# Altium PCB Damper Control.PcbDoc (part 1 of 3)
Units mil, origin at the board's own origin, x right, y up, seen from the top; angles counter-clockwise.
Board outline 4586.61 x 2962.6 mil, 4 copper layers (Top Layer, GND Plane, Power Plane, Bottom Layer), stack 70.356 mil thick; 195 components, 143 nets, 589 pads, 854 vias.
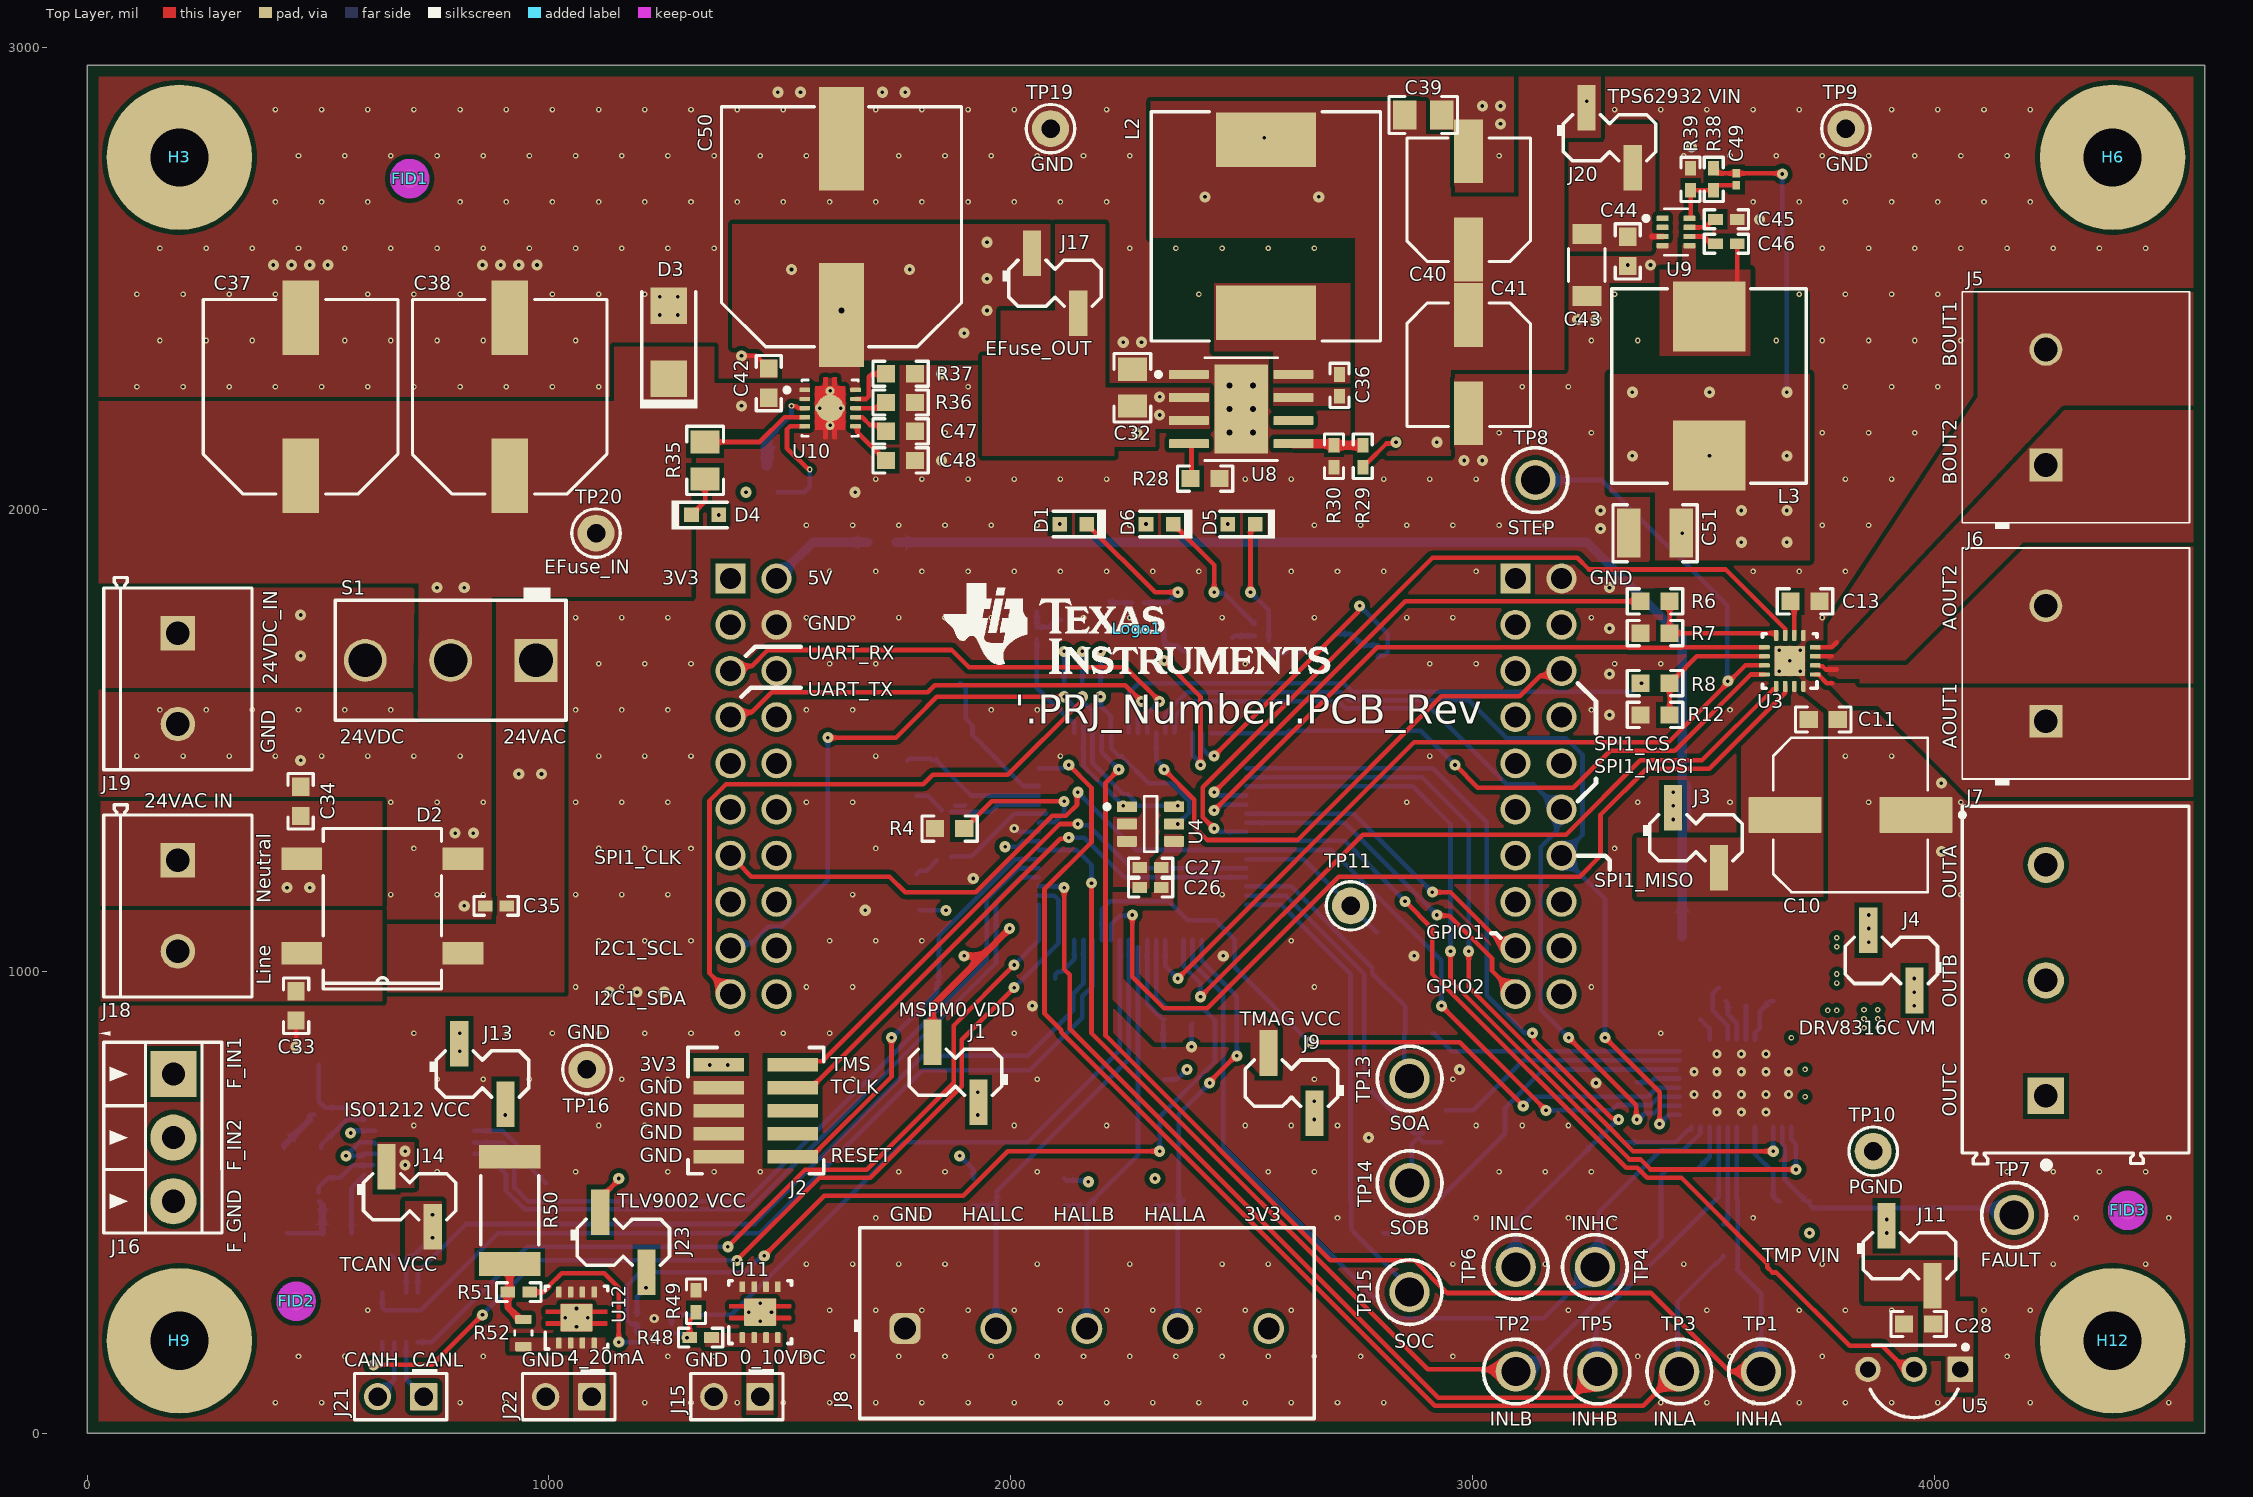
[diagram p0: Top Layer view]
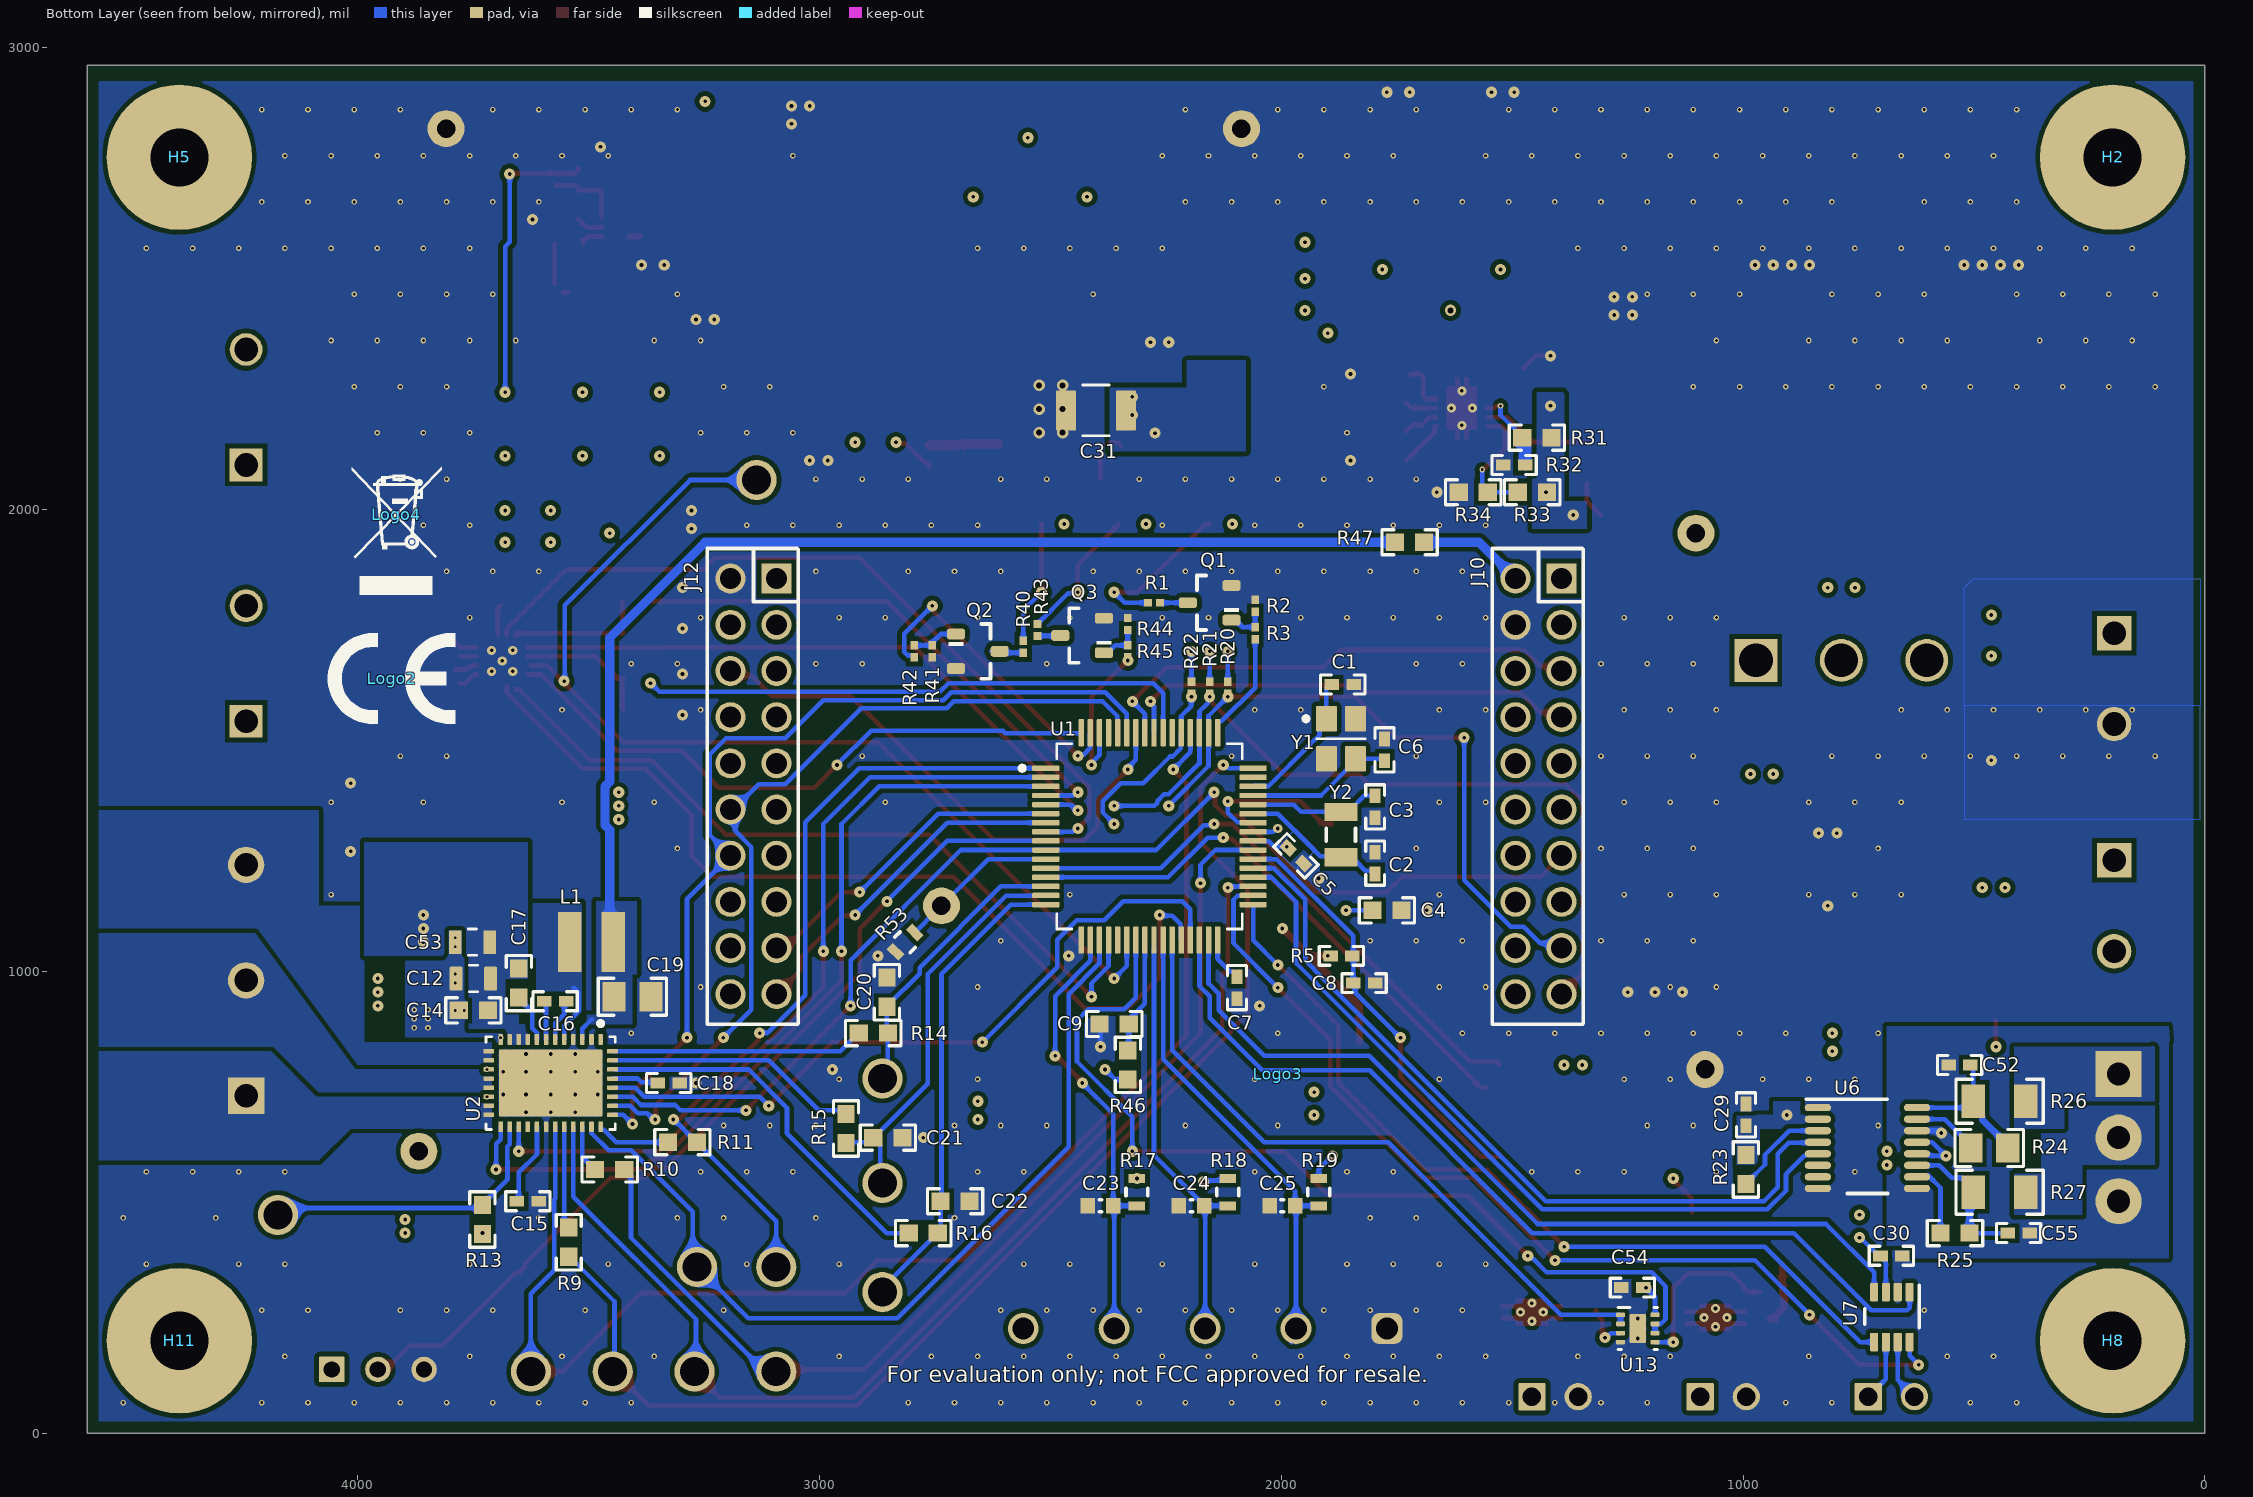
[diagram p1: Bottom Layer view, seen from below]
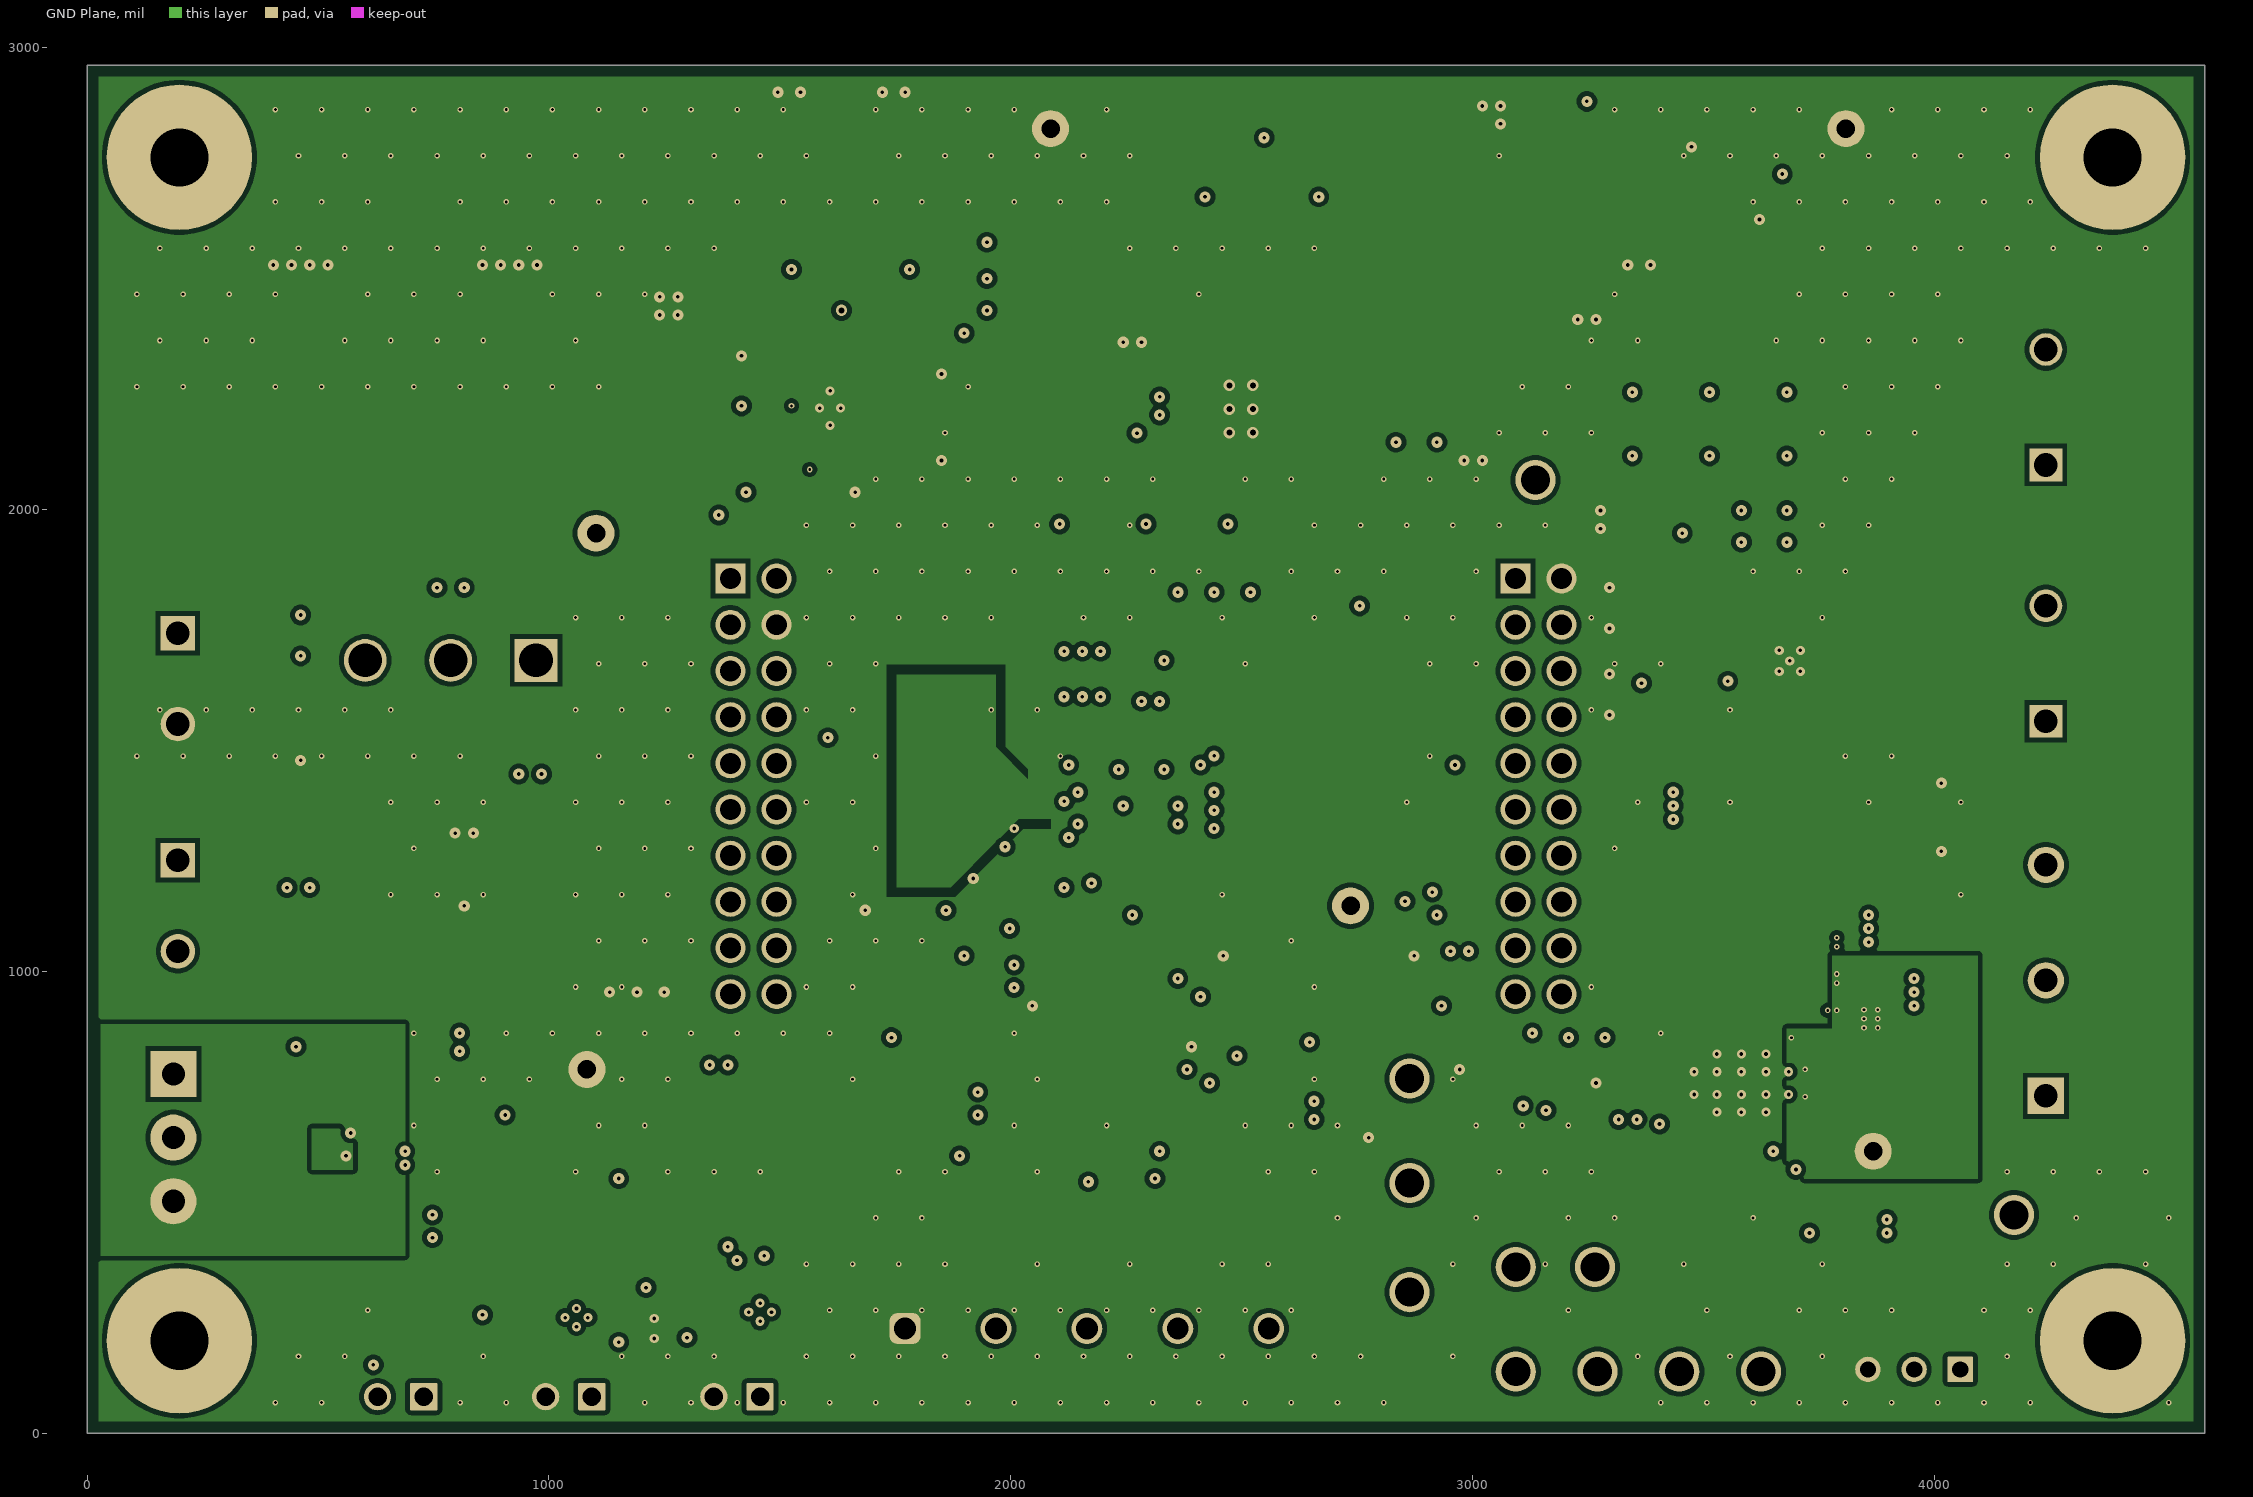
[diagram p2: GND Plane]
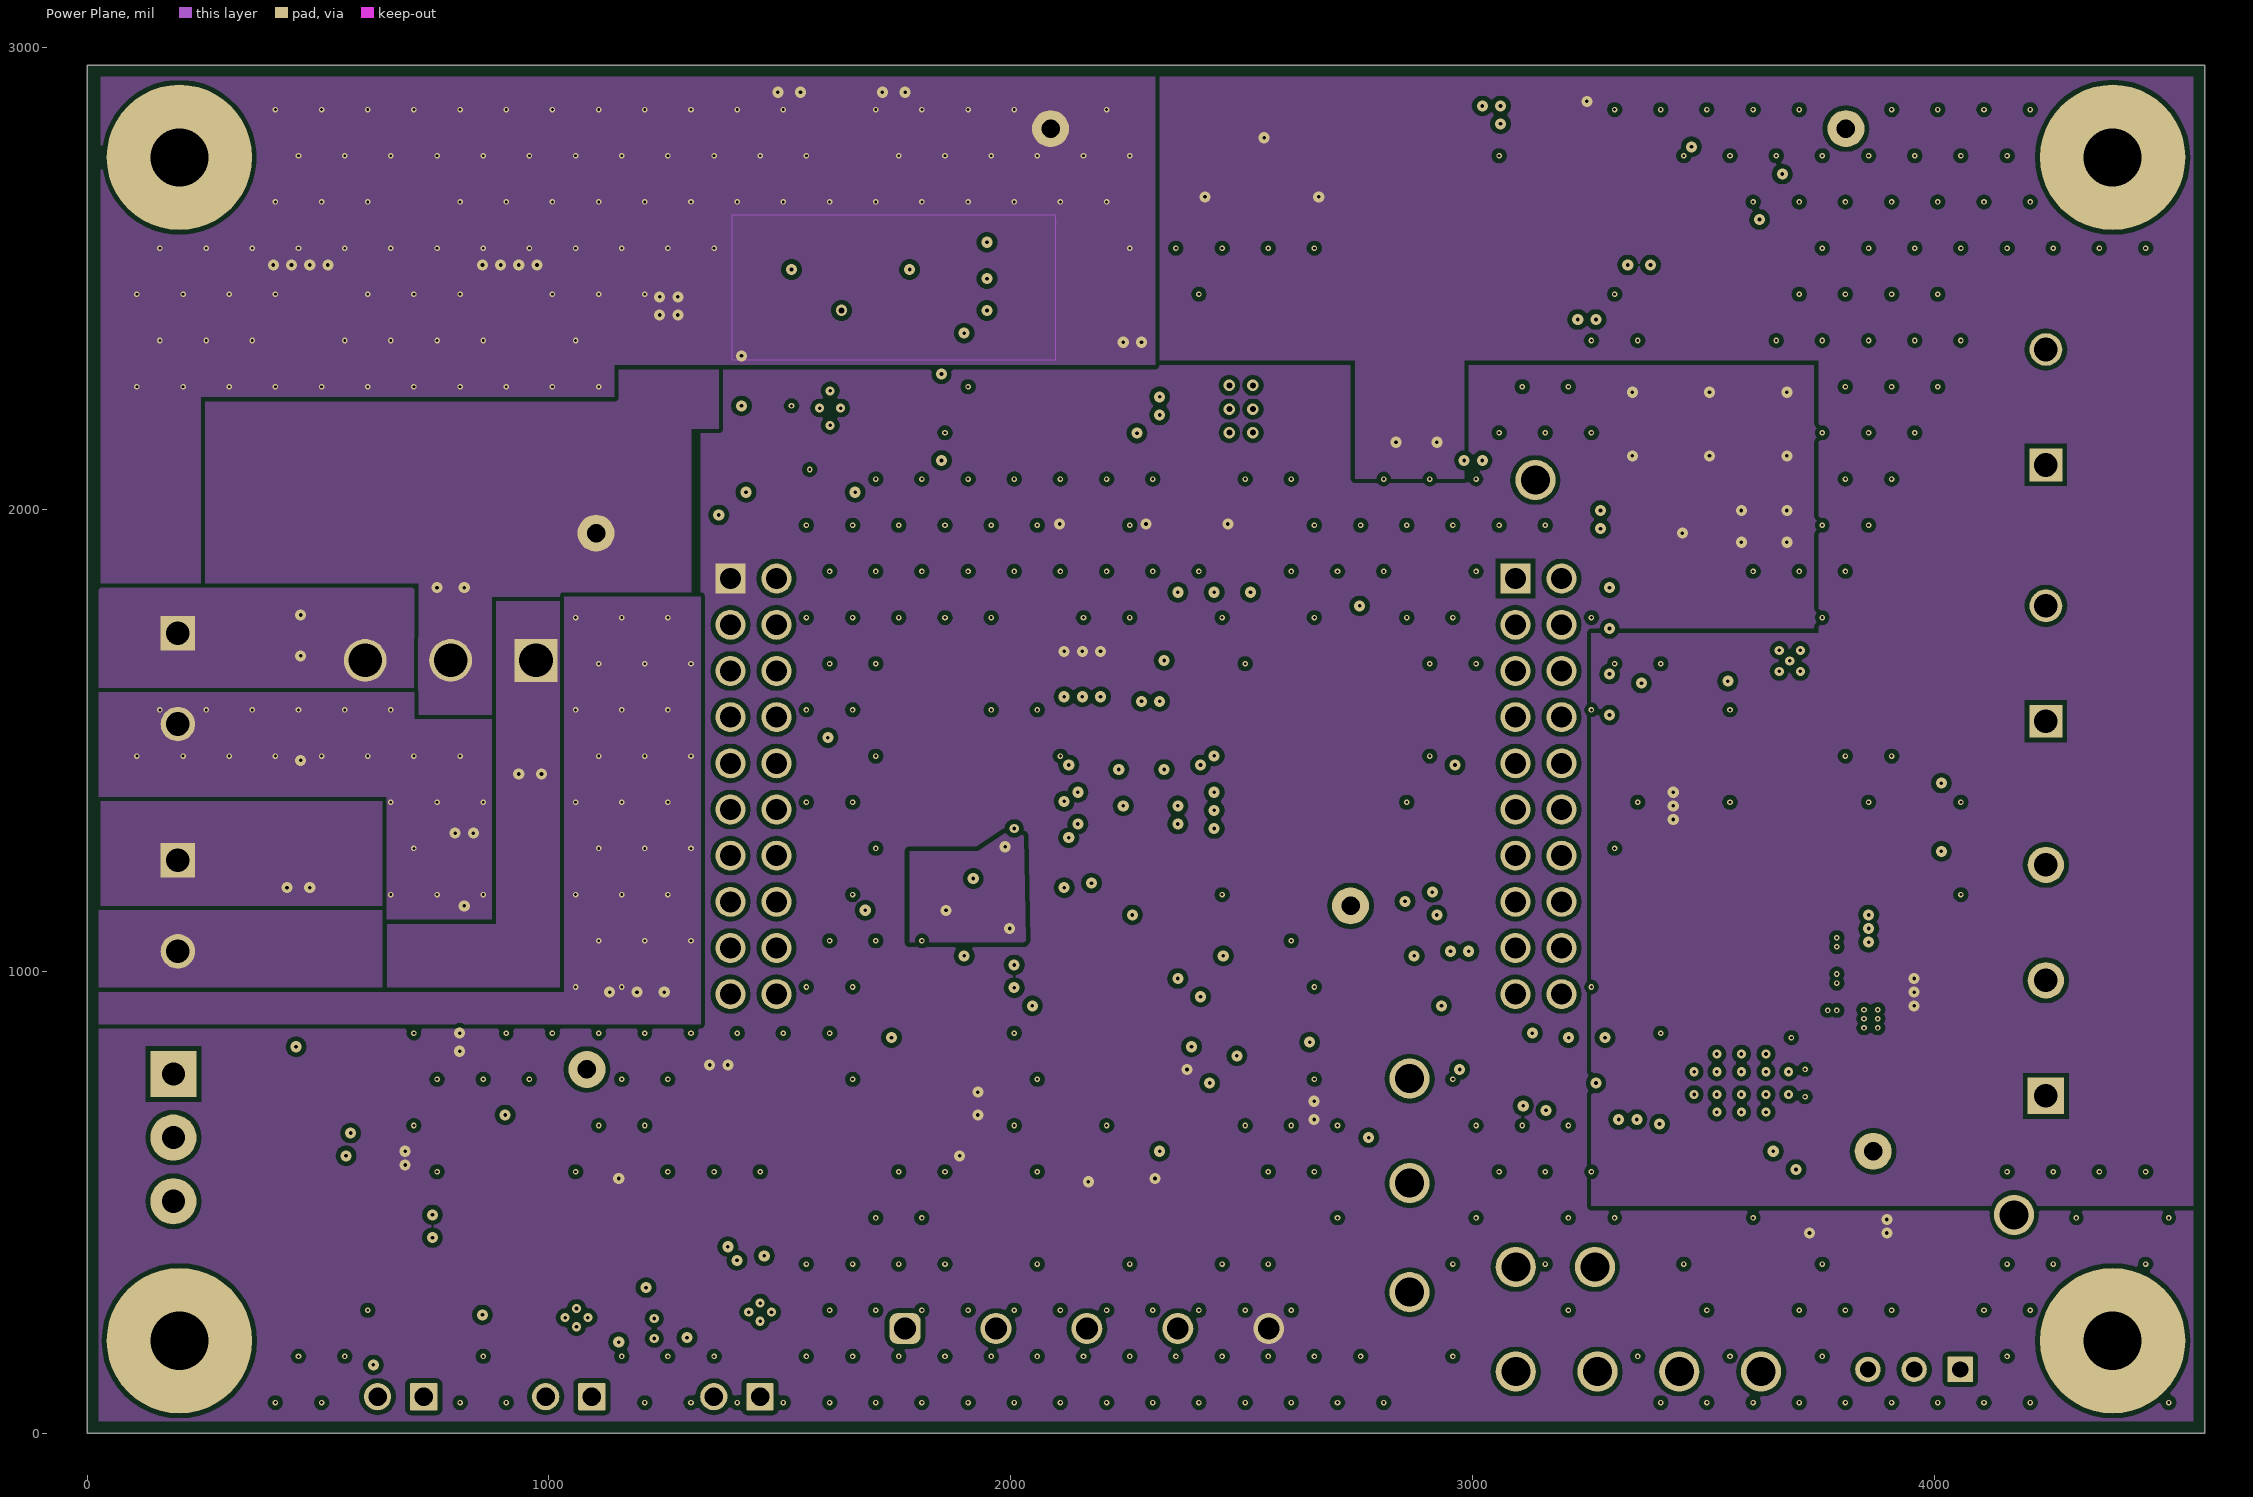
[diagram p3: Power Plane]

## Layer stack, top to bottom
Top Solder: solder mask 0.4, Solder Resist, Dk 3.5
Top Layer: signal copper 1.4
Dielectric 1: prepreg 2.8, PP-006, Dk 4.1
GND Plane: signal copper 1.378
Dielectric1: core 59.2, FR-4 High Tg, Dk 4.8
Power Plane: signal copper 1.378
Dielectric 2: prepreg 2.8, PP-006, Dk 4.1
Bottom Layer: signal copper 1.4
Bottom Solder: solder mask 0.4, Solder Resist, Dk 3.5

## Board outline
0,0 0,2962.6 4586.61,2962.6 4586.61,0

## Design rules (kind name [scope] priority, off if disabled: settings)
AcuteAngle [All] p1: minimum=4.50000000000000E+0001 checktracksonly=FALSE
AssemblyTestPointUsage [All] p1: valid=2
BoardOutlineClearance BoardOutlineClearance_MountingHoles [OnCopper and InComponentClass('Mounting Holes')] p1: gap=39.37 ignorepadtopadclearanceinfootprint=FALSE
BoardOutlineClearance BoardOutlineClearance_Poly [OnCopper and IsPoly] p2: gap=25 ignorepadtopadclearanceinfootprint=FALSE
BoardOutlineClearance [OnCopper and Not InComponentClass('Logo') and not InComponentClass('FiducialMark') and not InRegion(1000,500,4000,800) and not InPoly] p3: gap=40 ignorepadtopadclearanceinfootprint=FALSE
Clearance Clearance_Keepouts [((IsTrack Or IsArc) And Not InPoly) And IsFree and IsKeepOut vs ((IsTrack Or IsArc) And Not InPoly) And IsFree and IsKeepOut] p1: gap=0 ignorepadtopadclearanceinfootprint=FALSE
Clearance Clearance_Poly [InPolygon] p2: gap=10 ignorepadtopadclearanceinfootprint=TRUE
Clearance Clearance_FiducialMark [IsKeepOut and InComponentClass('FiducialMark') vs IsPad and InComponentClass('FiducialMark')] p3: gap=0 ignorepadtopadclearanceinfootprint=FALSE
Clearance [All] p4: gap=7.87 ignorepadtopadclearanceinfootprint=TRUE
ComponentClearance ComponentClearance_MountingHoles_FiducialMarks [InComponentClass('Mounting Holes') vs InComponentClass('FiducialMark')] p1: gap=50 collisioncheckmode=3 verticalgap=10 showdistances=FALSE
ComponentClearance ComponentClearance_Shunt [InComponentClass('Header') vs InComponentClass('Shunt')] p2: gap=0 collisioncheckmode=3 verticalgap=0 showdistances=FALSE
ComponentClearance ComponentClearance_Logo [InComponentClass('Logo')] p3: gap=30 collisioncheckmode=3 verticalgap=10 showdistances=FALSE
ComponentClearance ComponentClearance_ScrewToNut [(HasFootprint('NY PMS 440 0025 PH')) vs (HasFootprint('Keystone_1902C'))] p4: gap=5 collisioncheckmode=3 verticalgap=10 showdistances=FALSE
ComponentClearance ComponentClearance_MountingHoles [InComponentClass('Mounting Holes')] p5: gap=100 collisioncheckmode=3 verticalgap=100000 showdistances=FALSE
ComponentClearance ComponentClearance_SmallPassives [HasFootprint('0201*') or HasFootprint('0402*') or HasFootprint('0508') or HasFootprint('0603*') or HasFootprint('0612') or HasFootprint('0805*') or HasFootprint('0815*') or HasFootprint('0830*') or HasFootprint('1206*') or HasFootprint('1210*') or HasFootprint('1808*') or HasFootprint('1812*') or HasFootprint('1825*') or HasFootprint('2010*') or HasFootprint('2220*') or HasFootprint('2225*') or HasFootprint('2512*') or HasFootprint('2728*') or HasFootprint('3518*') vs HasFootprint('0201*') or HasFootprint('0402*') or HasFootprint('0508') or HasFootprint('0603*') or HasFootprint('0612') or HasFootprint('0805*') or HasFootprint('0815*') or HasFootprint('0830*') or HasFootprint('1206*') or HasFootprint('1210*') or HasFootprint('1808*') or HasFootprint('1812*') or HasFootprint('1825*') or HasFootprint('2010*') or HasFootprint('2220*') or HasFootprint('2225*') or HasFootprint('2512*') or HasFootprint('2728*') or HasFootprint('3518*')] p6: gap=14.96 collisioncheckmode=3 verticalgap=10 showdistances=FALSE
ComponentClearance ComponentClearance_THtoSMT [IsThruComponent vs IsSMTComponent] p7: gap=30 collisioncheckmode=3 verticalgap=30 showdistances=FALSE
ComponentClearance ComponentClearance_THtoTH [IsThruComponent vs IsThruComponent] p8: gap=20 collisioncheckmode=3 verticalgap=30 showdistances=FALSE
ComponentClearance [All] p9: gap=20 collisioncheckmode=3 verticalgap=10 showdistances=FALSE
DiffPairsRouting [All] p1: maxlimit=100 minlimit=10 mostfreqgap=10 toplayer_minwidth=15 toplayer_maxwidth=15 toplayer_prefwidth=15 midlayer1_minwidth=15 midlayer1_maxwidth=15 midlayer1_prefwidth=15 midlayer2_minwidth=15 midlayer2_maxwidth=15 midlayer2_prefwidth=15 bottomlayer_minwidth=15 bottomlayer_maxwidth=15 bottomlayer_prefwidth=15 maxuncoupledlength=1000
FabricationTestPointUsage TestPointUsage [All] p1: valid=2 allowmultiple=FALSE
FabricationTestpoint Testpoint [All] p1: side=3 testpointundercomponent=TRUE minsize=40 maxsize=100 preferedsize=60 minholesize=0 maxholesize=40 preferedholesize=32 testpointgrid=1 allowsidetop=TRUE allowsidebottom=TRUE usegrid=TRUE gridtolerance=0.01
FanoutControl Fanout_LCC [IsLCC] p1: bgadir=Out bgaviamode=Centered fanoutstyle=Auto fanoutdirection=Alternating viagrid=1 // Fanout_LCC (Default Rule)
FanoutControl Fanout_BGA [IsBGA] p2: bgadir=Out bgaviamode=Centered fanoutstyle=Auto fanoutdirection=Alternating viagrid=1 // Fanout_BGA (Default Rule)
FanoutControl Fanout_Default [All] p4: bgadir=Out bgaviamode=Centered fanoutstyle=Auto fanoutdirection=Alternating viagrid=1 // Fanout_Default (Default Rule)
FanoutControl Fanout_Small [(CompPinCount < 5)] p5: bgadir=Out bgaviamode=Centered fanoutstyle=Auto fanoutdirection=OutThenIn viagrid=1 // Fanout_Small (Default Rule)
HoleSize [All] p1: absolutevalues=TRUE maxlimit=251 minlimit=7.87 maxpercent=80.000 minpercent=20.000
MinimumAnnularRing MinimumAnnularRing_ThermalPadVias [IsVia and InAnyComponent] p1: minimumring=5.91
MinimumAnnularRing [All] p2: minimumring=7.87
MinimumSolderMaskSliver MinimumSolderMaskSliver_Logo [InComponentClass('Logo') vs InComponentClass('Logo')] p1: minsoldermaskwidth=0.7
MinimumSolderMaskSliver [All] p2: minsoldermaskwidth=3.94
PlaneConnect [All] p1: planeconnectstyle=Direct reliefexpansion=10 reliefentries=4 reliefconductorwidth=10 reliefairgap=10
PolygonConnect [All] p1: connectstyle=Direct reliefconductorwidth=10 reliefentries=4 polygonreliefangle="90 Angle" airgapwidth=10
RoutingLayers [All] p1: top layer_v5=TRUE mid layer 1_v5=FALSE mid layer 2_v5=FALSE bottom layer_v5=TRUE
RoutingVias ThermalPadVias [IsVia and InAnyComponent] p1: holewidth=7.87 width=19.68 viastyle="Through Hole" minholewidth=7.87 minwidth=19.68 maxholewidth=12.99 maxwidth=23.62
RoutingVias [All] p2: holewidth=16 width=34 viastyle="Through Hole" minholewidth=7.87 minwidth=24 maxholewidth=40 maxwidth=65
SilkToBoardRegionClearance [Not ((IsComment or IsDesignator) And (Hide <> 'False')) and not InRegion(1000,500,4000,800)] p1:
SilkToSilkClearance SilkToSilkClearance_Pb-FreeLogo [(HasFootprint('Pb-Free_Overlay_Medium') OR HasFootprint('Pb-Free_Overlay_Small')) vs (HasFootprint('Pb-Free_Overlay_Medium') OR HasFootprint('Pb-Free_Overlay_Small'))] p1: silktosilkclearance=0
SilkToSilkClearance [All] p2: silktosilkclearance=3.94
SilkToSolderMaskClearance SilkToComponentPadClearance [(IsPad or IsFill or IsRegion) and InAnycomponent] p1: minsilkscreentomaskgap=5 clearancetoexposedcopper=TRUE
SilkToSolderMaskClearance "Silk to Solder Mask Opening" [All] p2: minsilkscreentomaskgap=3.94 clearancetoexposedcopper=FALSE
SolderMaskExpansion [All] p1: expansion=1.97 istentingtop=FALSE
UnRoutedNet [All] p1: checkbadconnections=TRUE
Width [All] p1: maxlimit=100 minlimit=6 preferedwidth=10 checkconnectedcopper=TRUE
13 further rules are at their usual default settings.

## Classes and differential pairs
component class Power: C31 C32 C33 C34 C35 C36 C37 C38 C39 C40 C41 C42 C43 C44 C45 C46 C47 C48 C49 C50 C51 D2 D3 D4 J17 J18 J19 J20 L2 L3 R28 R29 R30 R31 R32 R33 R34 R35 R36 R37 R38 R39 S1 TP19 TP20 U8 U9 U10
component class "Interface and Peripherals": C26 C27 C28 C29 C30 C54 C55 J9 J10 J11 J12 J13 J14 J15 J16 J21 J22 J23 R20 R21 R22 R23 R24 R25 R26 R27 R47 R48 R49 R50 R51 R52 TP16 U4 U5 U6 U7 U11 U12 U13
component class Header: J1 J3 J4 J9 J11 J13 J14 J15 J17 J20 J21 J22 J23
component class "Damper Control_BlankSheet": C1 C2 C3 C4 C5 C6 C7 C8 C9 C10 C11 C12 C13 C14 C15 C16 C17 C18 C19 C20 C21 C22 C23 C24 C25 C53 D1 D5 D6 J1 J2 J3 J4 J5 J6 J7 J8 L1 Q1 Q2 Q3 R1 R2 R3 R4 R5 R6 R7 R8 R9 R10 R11 R12 R13 R14 R15 R16 R17 R18 R19 R40 R41 R42 R43 R44 R45 R46 R53 TP1 TP2 TP3 TP4 TP5 TP6 TP7 TP8 TP9 TP10 TP11 TP13 TP14 TP15 U1 U2 U3 Y1 Y2
component class "Mounting Holes": H3 H6 H9 H12
component class Logo: Logo1
component class "Damper Control_Hardware": FID1 FID2 FID3 H2 H3 H5 H6 H8 H9 H11 H12 Logo1 Logo2 Logo3 Logo4 ZZ1 ZZ2 ZZ3 ZZ4
component class FiducialMark: FID1 FID2 FID3
component class AssemblyNote: ZZ1 ZZ2 ZZ3 ZZ4

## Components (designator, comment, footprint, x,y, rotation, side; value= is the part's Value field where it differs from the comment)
C1 "GRM1555C1H220JA01D" 0402 1867.31,1620.86 r180 bottom value=22pF
C2 "GRM1555C1H220JA01D" 0402 1797.14,1234.28 r90 bottom value=22pF
C3 "GRM1555C1H220JA01D" 0402 1797.14,1356.19 r270 bottom value=22pF
C4 "GRM188R60J106ME84" 0603 1771.65,1131.89 r180 bottom value=10uF
C5 "GRM155R60J104KA01D" 0402 1968.5,1250 r225 bottom value=0.1uF
C6 "GRM1555C1H220JA01D" 0402 1776.64,1479.44 r90 bottom value=22pF
C7 "GRM155R60J474KE19D" 0402 2096.46,964.57 r270 bottom value=0.47uF
C8 "GRM155R60J103KA01D" 0402 1820.87,974.41 r180 bottom value=0.01uF
C9 "C1608X5R1E105K080AC" 0603 2362.2,885.83 r0 bottom value=1uF
C10 "107AXZ050M" FP-107AXZ050M_RADIAL-MFG 3818.9,1338.58 r180 top value=100µF
C11 "C1608X5R1H104K080AA" 0603 3759.84,1545.28 r0 top value=0.1uF
C12 "GRM21BR61H106ME43L" FP-GRM21BR61H106ME43L_0805-MFG 3750,984.25 r180 bottom value=10µF
C13 "GRM188R70J474KA01D" 0603 3720.47,1801.18 r0 top value=0.47uF
C14 "C1608X5R1H104K080AA" 0603 3750,915.35 r0 bottom value=0.1uF
C15 "GRM155R60J105KE19D" 0402 3631.89,501.97 r180 bottom value=1uF
C16 "GRM155R61H473ME14D" 0402 3572.83,935.04 r180 bottom value=0.047uF
C17 "C0603C105K4PACTU" 0603 3651.57,974.41 r270 bottom value=1uF
C18 "GRM155R60J104KA01D" 0402 3326.77,757.87 r180 bottom value=0.1uF
C19 "NMC0805X5R226M35TRPLPF" 0805_HV 3405.51,944.88 r0 bottom value=22uF
C20 "GRM1885C1H300JA01D" 0603 2854.33,954.72 r90 bottom value=30pF
C21 "GRM1885C1H300JA01D" 0603 2852.36,639.76 r180 bottom value=30pF
C22 "GRM1885C1H300JA01D" 0603 2706.69,501.97 r180 bottom value=30pF
C23 "885012206034" 0603L 2391.73,492.13 r0 bottom value=1000pF
C24 "885012206034" 0603L 2194.88,492.13 r0 bottom value=1000pF
C25 "885012206034" 0603L 1998.03,492.13 r0 bottom value=1000pF
C26 "GRM155R61E105KA12D" 0402 2303.15,1181.1 r180 top value=1uF
C27 "GRM155R71H104ME14D" 0402 2303.15,1224.52 r180 top value=0.1uF
C28 "C0603C104K9PAC7867" 0603 3966.54,236.22 r180 top value=0.1uF
C29 "GRM155R61A104KA01D" 0402 994.09,688.98 r90 bottom value=0.1uF
C30 "GRM155R61A104KA01D" 0402 679.13,383.86 r180 bottom value=0.1uF
C31 "C3225X7R2A225K230AB" FP-C3225X7R2A225K230AB_1210-MFG 2401.57,2214.57 r180 bottom value=2.2µF
C32 "C2012X7R2A104K125AA" 0805_HV 2263.78,2263.78 r90 top value=0.1uF
C33 "C1608X7S2A683K080AB" 0603 452.76,925.2 r270 top value=0.068uF
C34 "C1608X7S2A683K080AB" 0603 462.6,1368.11 r90 top value=0.068uF
C35 "CGA2B3X7S2A103K050BB" 0402 885.83,1141.73 r180 top value=0.01uF
C36 "GRM155R71C104KA88D" 0402 2712.37,2268.7 r270 top value=0.1uF
C37 "EEE-FK1J101P" SM_RADIAL_G 462.6,2244.09 r90 top value=100uF
C38 "EEE-FK1J101P" SM_RADIAL_G 915.35,2244.09 r90 top value=100uF
C39 "C2012X5R1H475K125AB" 0805_HV 2893.7,2854.33 r0 top value=4.7uF
C40 "50SVPF10M" CAPSMT_62_F61 2993.1,2668.32 r90 top value=10uF
C41 "50SVPF10M" CAPSMT_62_F61 2991.16,2315.93 r270 top value=10uF
C42 "C1608X5R1H105K080AB" 0603 1476.38,2273.62 r90 top value=1uF
C43 "C3216X5R1H106K160AB" 1206_180 3248.03,2529.53 r270 top value=10uF
C44 "CGA3E2X7R1H104K080AA" 0603 3336.61,2559.06 r270 top value=0.1uF
C45 "GRM155R71A333KA01D" 0402 3550.24,2628.4 r0 top value=0.033uF
C46 "GRM155R71A104KA01D" 0402 3550.24,2575.48 r180 top value=0.1uF
C47 "C1608X5R1H154K080AB" 0603 1761.81,2169.38 r180 top value=0.15uF
C48 "GRM188R71H123KA01D" 0603 1761.81,2106.3 r180 top value=0.012uF
C49 "GRM0335C1E470JA01D" 0201_033 3571.9,2715.01 r270 top value=47pF
C50 "EMVH630ARA101MKE0S" CAPSMT_62_KE0 1633.86,2612.2 r90 top value=100uF
C51 "GRM32ER61C476KE15L" 1210_270 3395.67,1948.82 r180 top value=47uF
C52 "GRM155R71H103KA88D" 0402 531.5,797.24 r0 bottom value=0.01uF
C53 "GRM21BR61H106ME43L" FP-GRM21BR61H106ME43L_0805-MFG 3751.97,1062.99 r180 bottom value=10µF
C54 "GRM155R61A104KA01D" 0402 1240.16,314.96 r180 bottom value=0.1uF
C55 "GRM155R71H103KA88D" 0402 403.54,433.07 r180 bottom value=0.01uF
D1 "LTST-C191TGKT" LTST-C191_Green 2135.83,1968.5 r0 top value=Green
D2 "DF1501S-E3/77" DF-S 639.76,1141.73 r180 top value=100V
D3 "SMAJ40A" SMA 1259.84,2362.2 r90 top value=40V
D4 "LTST-C191KRKT" LTST-C191_Red 1338.58,1988.19 r180 top value=Red
D5 "LTST-C191KRKT" LTST-C191_Red 2500,1968.5 r0 top value=Red
D6 "LTST-C191KFKT" LTST-C191_Orange 2322.83,1968.5 r0 top value=Orange
FID1 "Fiducial" Fiducial10-20 698.82,2716.54 r0 top
FID2 "Fiducial" Fiducial10-20 452.76,285.43 r0 top
FID3 "Fiducial" Fiducial10-20 4419.29,482.28 r0 top
H2 "1902C" Keystone_1902C 200,2762.6 r180 bottom
H3 "NY PMS 440 0025 PH" "NY PMS 440 0025 PH" 200,2762.6 r0 top
H5 "1902C" Keystone_1902C 4386.61,2762.6 r180 bottom locked
H6 "NY PMS 440 0025 PH" "NY PMS 440 0025 PH" 4386.61,2762.6 r0 top locked
H8 "1902C" Keystone_1902C 200,200 r180 bottom locked
H9 "NY PMS 440 0025 PH" "NY PMS 440 0025 PH" 200,200 r0 top locked
H11 "1902C" Keystone_1902C 4386.61,200 r180 bottom
H12 "NY PMS 440 0025 PH" "NY PMS 440 0025 PH" 4386.61,200 r0 top locked
J1 "M20-8770246" Harwin_M20-87702 1880.71,781.3 r180 top
J2 "FTSH-105-01-F-DV-K" Samtec_FTSH-105-01-x-DV-K 1448.23,698.03 r0 top
J3 "M20-8770246" Harwin_M20-87702 3484.25,1289.37 r0 top
J4 "M20-8770246" Harwin_M20-87702 3907.48,1023.62 r180 top
J5 "1714955" Phoenix_1714955 4242.13,2221.46 r90 top
J6 "1714955" Phoenix_1714955 4242.13,1666.34 r90 top
J7 "1714968" Phoenix_1714968 4242.13,980.32 r90 top
J8 "1792892" Phoenix_1792892 2165.35,226.38 r0 top
J9 "M20-8770246" Harwin_M20-87702 2608.27,757.87 r180 top
J10 "SSW-110-23-F-D" CONN_SSW-110-23-F-D 1443.31,1400.39 r90 bottom
J11 "M20-8770246" Harwin_M20-87702 3946.85,383.86 r0 top
J12 "SSW-110-23-F-D" CONN_SSW-110-23-F-D 3143.31,1400.39 r90 bottom
J13 "M20-8770246" Harwin_M20-87702 856.3,777.56 r0 top
J14 "M20-8770246" Harwin_M20-87702 698.82,511.81 r0 top
J15 "PEC02SAAN" CONN_PEC02SAAN 1407.48,78.74 r180 top
J16 "ED555/3DS" TERM_BLK_ED555-3DS 187.01,777.56 r270 top
J17 "M20-8770246" Harwin_M20-87702 2096.46,2490.16 r0 top
J18 "1729018" Phoenix_1729018 196.85,1141.73 r270 top
J19 "1729018" Phoenix_1729018 196.85,1633.86 r270 top
J20 "M20-8770246" Harwin_M20-87702 3297.24,2805.12 r0 top
J21 "PEC02SAAN" CONN_PEC02SAAN 679.13,78.74 r180 top
J22 "PEC02SAAN" CONN_PEC02SAAN 1043.31,78.74 r180 top
J23 "M20-8770246" Harwin_M20-87702 1161.42,413.39 r0 top
L1 "NPI32C470MTRF" NPI32C 3494.09,1062.99 r180 bottom value=47uH
L2 "MSS1210-683ME" MSS1210 2552.68,2613.35 r90 top value=68uH
L3 "744325780" WE-HCI_1050 3512.84,2267.13 r0 top
Logo1 "Texas Instruments" TI_Stacked_Overlay_Small 2273.62,1742.13 r0 top
Logo2 "CE Mark" CE_Mark_5mm 3927.17,1633.86 r180 bottom
Logo3 "FCC disclaimer" FCC_disclaimer 2007.87,777.56 r180 bottom
Logo4 "WEEE logo" WEEE_Minimum 3917.32,1988.19 r180 bottom
Q1 "MMBT2222ALT1G" SOT-23 2155.44,1798.05 r0 bottom value="40 V"
Q2 "MMBT2222ALT1G" SOT-23 2657.48,1692.91 r180 bottom value="40 V"
Q3 "MMBT2222ALT1G" SOT-23 2431.62,1727.18 r0 bottom value="40 V"
R1 "RC0201FR-07100RL" 0201 2275.99,1798.05 r0 bottom value=100
R2 "RC0201FS-7D100KL" 0201 2057.09,1791.34 r270 bottom value=100k
R3 "RC0201JR-074K7L" 0201 2057.09,1732.28 r90 bottom value=4.7k
R4 "RT0603BRD07100KL" 0603 1868.11,1309.06 r180 top value=100k
R5 "CRCW040247K0JNED" 0402 1870.08,1033.46 r0 bottom value=47k
R6 "CRCW06030000Z0EA" 0603 3395.67,1801.18 r0 top value=0
R7 "CRCW06030000Z0EA" 0603 3395.67,1732.28 r0 top value=0
R8 "CRCW06030000Z0EA" 0603 3395.67,1624.02 r0 top value=0
R9 "CRCW06030000Z0EA" 0603 3543.31,413.39 r90 bottom value=0
R10 "CRCW06030000Z0EA" 0603 3454.72,570.87 r0 bottom value=0
R11 "CRCW06030000Z0EA" 0603 3297.24,629.92 r0 bottom value=0
R12 "CRCW06030000Z0EA" 0603 3395.67,1555.12 r0 top value=0
R13 "CRCW06035K10JNEA" 0603 3730.32,462.6 r90 bottom value=5.1k
R14 "CRCW06031K00JNEA" 0603 2883.86,866.14 r180 bottom value=1.0k
R15 "CRCW06031K00JNEA" 0603 2942.91,659.45 r270 bottom value=1.0k
R16 "CRCW06031K00JNEA" 0603 2775.59,433.07 r180 bottom value=1.0k
R17 "TNPW060310K0BEEA" TNPW0603 2312.99,521.65 r90 bottom value=10.0k
R18 "TNPW060310K0BEEA" TNPW0603 2116.14,521.65 r90 bottom value=10.0k
R19 "TNPW060310K0BEEA" TNPW0603 1919.29,521.65 r90 bottom value=10.0k
R20 "RC0201JR-7D4K7L" 0201 2116.14,1614.17 r90 bottom value=4.7k
R21 "RC0201JR-7D4K7L" 0201 2155.51,1614.17 r90 bottom value=4.7k
R22 "RC0201JR-7D4K7L" 0201 2194.88,1614.17 r90 bottom value=4.7k
R23 "CRCW06030000Z0EA" 0603 994.09,570.87 r90 bottom value=0
R24 "RG2012P-5620-B-T5" 0805_HV 467.23,617.29 r180 bottom value=562
R25 "RT0603DRE07200RL" 0603 541.34,433.07 r180 bottom value=200
R26 "RP73D2B1K0BTG" 1206 444.88,718.5 r180 bottom value=1.00k
R27 "RP73D2B1K0BTG" 1206 444.88,521.65 r180 bottom value=1.00k
R28 "CRCW060364K9FKEA" 0603 2421.26,2066.93 r180 top value=64.9k
R29 "CRCW0402100KFKED" 0402 2762.87,2115.34 r270 top value=100k
R30 "CRCW04027K15FKED" 0402 2700.37,2115.34 r90 top value=7.15k
R31 "MCT06030C1004FP500" 0603 1446.85,2155.51 r180 bottom value=1.00Meg
R32 "CRCW040238K3FKED" 0402 1496.06,2096.46 r180 bottom value=38.3k
R33 "CRCW0603100KJNEA" 0603 1456.69,2037.4 r0 bottom value=100k
R34 "CRCW060312K1FKEA" 0603 1584.65,2037.4 r180 bottom value=12.1k
R35 "CRCW080513K7FKEA" 0805_HV 1338.58,2106.3 r270 top value=13.7k
R36 "CRCW060395K3FKEA" 0603 1761.81,2231.58 r0 top value=95.3k
R37 "CRCW06038K20JNEA" 0603 1761.81,2293.92 r0 top value=8.2k
R38 "CRCW040230K9FKED" 0402 3522.68,2715.01 r90 top value=30.9k
R39 "CRCW040210K0FKED" 0402 3472.65,2715.01 r270 top value=10.0k
R40 "RC0201FR-07261RL" 0201 2559.06,1702.76 r90 bottom value=261
R41 "RC0201FS-7D100KL" 0201 2755.91,1692.91 r90 bottom value=100k
R42 "RC0201JR-074K7L" 0201 2795.28,1692.91 r90 bottom value=4.7k
R43 "RC0201FR-07261RL" 0201 2528.17,1738.99 r90 bottom value=261
R44 "RC0201FS-7D100KL" 0201 2332.68,1751.97 r270 bottom value=100k
R45 "RC0201JR-074K7L" 0201 2332.68,1692.91 r90 bottom value=4.7k
R46 "RC0603JR-070RL" 0603 2332.68,797.24 r90 bottom value=0
R47 "CRCW06030000Z0EA" 0603 1722.44,1929.13 r0 bottom value=0
R48 "CRCW0402158KFKED" 0402 1328.74,206.69 r0 top value=158k
R49 "CRCW040249K9FKED" 0402 1318.9,285.43 r270 top value=49.9k
R50 "CRCW040210K0FKED" 0402 935.04,305.12 r180 top value=10.0k
R51 "CRCW2512120RFKEG" 2512 915.35,482.28 r270 top value=120
R52 "TNPW060312K0BYEN" FP-TNPW060312K0BYEN_0603-MFG 944.88,216.54 r90 top value=12k
R53 "TNPW060310K0BEEA" TNPW0603 2814.96,1062.99 r315 bottom value=10.0k
S1 "1103M2S3CQE2" SW_1103M2S3CQE2 787.4,1673.23 r180 top
TP1 "INHA" Keystone5122 3625.31,133.19 r0 top
TP2 "INLB" Keystone5122 3094.17,133.19 r0 top
TP3 "INLA" Keystone5122 3448.26,133.19 r0 top
TP4 "INHC" Keystone5122 3265.36,359.57 r0 top
TP5 "INHB" Keystone5122 3271.22,133.19 r0 top
TP6 "INLC" Keystone5122 3094.17,359.57 r0 top
TP7 "5122" Keystone5122 4173.23,472.44 r0 top
TP8 "STEP" Keystone5122 3136.51,2063.8 r0 top
TP9 "GND" Keystone5001 3809.06,2824.8 r90 top
TP10 "PGND" Keystone5001 3868.11,610.24 r90 top
TP11 "5117" Keystone5117 2736.22,1141.73 r90 top
TP13 "5122" Keystone5122 2864.17,767.63 r0 top
TP14 "5122" Keystone5122 2864.17,541.25 r0 top
TP15 "5122" Keystone5122 2864.17,305.12 r0 top
TP16 "GND" Keystone5001 1082.68,787.4 r270 top
TP19 "GND" Keystone5001 2086.61,2824.8 r90 top
TP20 "EFuse_IN" Keystone5000 1102.36,1948.82 r90 top
U1 "MSPM0G3507SPM" PM0064A-MFG 2285.84,1292.12 r180 bottom
U2 "DRV8316CRRGFR" RGF0040E-MFG 3582.68,757.87 r270 bottom
U3 "DRV8428RTER" RTE0016J 3687.39,1672.24 r180 top
U4 "TMAG5273DBV" DBV0006A-MFG 2303.15,1318.9 r0 top
U5 "TMP235LP" LP0003A 3956.69,137.8 r270 top
U6 "ISO1212DBQR" DBQ0016A_N 730.93,617.29 r180 bottom
U7 "TCAN334GDCNR" DCN0008A_N 678.15,250.98 r270 bottom
U8 "LMR38020SDDA" DDA0008E-MFG 2499.38,2217.52 r0 top
U9 "TPS62932DRLR" DRL0008A-MFG 3441.15,2601.07 r0 top
U10 "TPS16410DRC" DRC0010J-MFG 1609.33,2219.62 r0 top
U11 "TVS1401DRBT" DRB0008A 1457.68,261.81 r90 top
U12 "TVS1401DRBT" DRB0008A 1060.04,250 r90 top
U13 "TLV9002IDSGR" DSG0008A 1228.35,226.38 r180 bottom
Y1 "X1E0000210179" FP-X1E0000210179_TSX-3225-MFG 1871.25,1503.57 r270 bottom
Y2 "X1A0001410014" Epson_FC-135 1871.25,1296.06 r270 bottom
ZZ1 "This Assembly Note is for PCB labels only" AssemblyNoteLabel 185,3938 r0 top
ZZ2 "These assemblies are ESD sensitive, ESD precautions shall be observed." AssemblyNote 185,3829.11 r0 top
ZZ3 "These assemblies must be clean and free from flux and all contaminants. Use of no clean flux is not acceptable." AssemblyNote 185,3740.56 r0 top
ZZ4 "These assemblies must comply with workmanship standards IPC-A-610 Class 2, unless otherwise specified." AssemblyNote 185,3652 r0 top

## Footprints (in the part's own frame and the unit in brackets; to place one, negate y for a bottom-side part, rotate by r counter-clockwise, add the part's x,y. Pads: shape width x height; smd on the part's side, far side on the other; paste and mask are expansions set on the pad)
0201 [mm] "Data from Kemet datasheet CC101_COM dated 7/28/11"
  rect 0.46x0.42 smd mask+0.048: 1(-0.33,0) 2(0.33,0)
  body extent -0.31,-0.16 0.31,0.16, height 0.26
0201_033 [mm] "SMD, 2-Leads, Height 0.33mm"
  rect 0.46x0.42 smd mask+0.048: 1(-0.33,0) 2(0.33,0)
  body extent -0.31,-0.16 0.31,0.16, height 0.33
0402 [mm] "0402 from SM-752 data"
  rect 0.8x0.6 smd: 1(-0.6,0) 2(0.6,0)
  silkscreen extent -1.22,-0.52 1.22,0.52, body extent -0.55,-0.3 0.55,0.3, height 0.6
0603 [mm] "0603 from SM-752 data"
  rect 1x0.95 smd: 1(-0.8,0) 2(0.8,0)
  silkscreen extent -1.52,-0.69 1.52,0.69, body extent -0.87,-0.47 0.87,0.47, height 1
0603L [mm] "0603 from SM-752 data"
  rect 0.8x0.85 smd: 1(-0.7,0) 2(0.7,0)
  silkscreen extent -0.07,-0.33 0.07,0.33, body extent -0.87,-0.47 0.87,0.47, height 1
0805_HV [mil] "0805 with 30mil clearance between pads"
  rect 50x63 smd: 1(-40,0) 2(40,0)
  silkscreen extent -74,-40 74,40, body extent -43,-29 43,29, height 57
1206 [mm] "1206 from SM-752 data"
  rect 1.3x1.85 smd: 1(-1.45,0) 2(1.45,0)
  silkscreen extent -2.4,-1.21 2.4,1.21, body extent -1.7,-0.9 1.7,0.9, height 1.35
1206_180 [mm] "1206_180"
  rect 1.1x1.6 smd: 1(-1.7,0) 2(1.7,0)
  silkscreen extent -0.9,-1 0.9,1, body extent -1.75,-0.95 1.75,0.95, height 1.8
1210_270 [mm] "1210"
  rect 1.3x2.7 smd: 1(-1.45,0) 2(1.45,0)
  silkscreen extent -2.32,-1.57 2.32,1.57, body extent -1.7,-1.35 1.7,1.35, height 2.7
2512 [mm] "Chip Resistor, Body 6.3x3.2mm, IPC Medium Density"
  rect 1.3x3.4 smd: 1(-2.95,0) 2(2.95,0)
  silkscreen extent -1.9,-1.6 1.9,1.6, body extent -3.22,-1.67 3.22,1.67, height 0.71
AssemblyNote [mil] "Assembly Note"
AssemblyNoteLabel [mil] "Assembly Note for PCB Labels"
CAPSMT_62_F61 [mm] "6.3 x 5.8mm:  Chemi-Con F61"
  rect 3.5x1.6 smd: 1(-2.675,0.025) 2(2.725,0.025)
  silkscreen extent -3.34,-3.38 3.46,3.42, body extent -3.37,-3.38 3.46,3.43, height 6.1
CAPSMT_62_KE0 [mm] "12.5 x 13.5mm:  Chemi-Con KE0"
  rect 5.7x2.5 smd: 1(-4.85,0) 2(4.85,0)
  silkscreen extent -6.6,-6.6 6.6,6.6, body extent -6.6,-6.6 6.6,6.6, height 14
CE_Mark_5mm [mil] "Minimum text height for CE Mark"
  silkscreen extent -138,-98 138,98
CONN_PEC02SAAN [mm] "SULLINS"
  rrect7% 1.5x1.5 hole 1.016: 1(-1.27,0)
  round 1.5 hole 1.016: 2(1.27,0)
  silkscreen extent -2.54,-1.52 2.54,1.27, body extent -2.54,-1.27 2.54,1.27, height 8.38
CONN_SSW-110-23-F-D [mm] "SAMTEC"
  rect 1.65x1.65 hole 1.15: 1(11.43,-1.27)
  round 1.65 hole 1.15: 2(11.43,1.27) 3(8.89,-1.27) 4(8.89,1.27) 5(6.35,-1.27) 6(6.35,1.27) 7(3.81,-1.27) 8(3.81,1.27) 9(1.27,-1.27) 10(1.27,1.27) 11(-1.27,-1.27) 12(-1.27,1.27) 13(-3.81,-1.27) 14(-3.81,1.27) 15(-6.35,-1.27) 16(-6.35,1.27) 17(-8.89,-1.27) 18(-8.89,1.27) 19(-11.43,-1.27) 20(-11.43,1.27)
  silkscreen extent -13.08,-2.46 13.08,2.54, body extent -13,-2.51 13,2.54, height 8.59
DBQ0016A_N [mm] "SOP, 16-Leads, Body 4.9x3.9mm, Pitch 0.635mm, IPC Medium Density"
  oval 1.45x0.4 smd: 1(-2.725,2.223) 2(-2.725,1.588) 3(-2.725,0.953) 4(-2.725,0.318) 5(-2.725,-0.317) 6(-2.725,-0.952) 7(-2.725,-1.587) 8(-2.725,-2.222) 9(2.725,-2.223) 10(2.725,-1.588) 11(2.725,-0.953) 12(2.725,-0.318) 13(2.725,0.317) 14(2.725,0.952) 15(2.725,1.587) 16(2.725,2.222)
  silkscreen extent -3.35,-2.5 1.1,2.68, body extent -3.01,-2.45 3.01,2.45, height 1.63
DBV0006A-MFG [mm]
  rrect17% 1.1x0.6 smd paste+0 mask+0: 1(-1.3,0.95) 2(-1.3,0) 3(-1.3,-0.95) 4(1.3,-0.95) 5(1.3,0) 6(1.3,0.95)
  silkscreen extent -2.52,-1.53 0.35,1.53, body extent -1.95,-1.78 1.95,1.78, height 0.25
DCN0008A_N [mm] "SOP, 8-Leads, Body 2.9x1.6mm, Pitch 0.65mm, IPC Medium Density"
  rrect22% 1x0.45 smd: 1(-1.375,0.975) 2(-1.375,0.325) 3(-1.375,-0.325) 4(-1.375,-0.975) 5(1.375,-0.975) 6(1.375,-0.325) 7(1.375,0.325) 8(1.375,0.975)
  silkscreen extent -1.75,-1.5 0.58,1.5, body extent -1.41,-1.45 1.41,1.45, height 1.45
DDA0008E-MFG [mm]
  rrect20% 2.2x0.5 smd paste-1000 mask+0: 1(-2.875,1.905) 2(-2.875,0.635) 3(-2.875,-0.635) 4(-2.875,-1.905) 5(2.875,-1.905) 6(2.875,-0.635) 7(2.875,0.635) 8(2.875,1.905)
  rrect3% 2.95x4.9 smd paste-1000 mask-1000: 9(0,0)
  silkscreen extent -4.67,-2.83 2,2.83, body extent -3,-2.45 3,2.45, height 1.7
DF-S [mil] "Diodes Inc. recommended land pattern per ap02001.pdf rev 30"
  rect 88x49 smd: 1(-174.5,102.36) 2(-174.5,-102.36) 3(174.5,-102.36) 4(174.5,102.36)
  silkscreen extent -128,-168 128,180, body extent -205,-168 205,168, height 108
DRB0008A [mm] "VSON-8"
  rrect32% 0.6x0.31 smd: 1(-1.4,0.975) 2(-1.4,0.325) 3(-1.4,-0.325) 4(-1.4,-0.975) 5(1.4,-0.975) 6(1.4,-0.325) 7(1.4,0.325) 8(1.4,0.975)
  rrect7% 1.5x1.75 smd paste-0.75: 9(0,0)
  Top Layer region: -0.7,-0.875 -0.49,-0.875 -0.471,-0.879 -0.455,-0.89 -0.444,-0.906 -0.44,-0.925 -0.44,-0.925 -0.44,-1.65 -0.436,-1.669 -0.425,-1.685 -0.409,-1.696 -0.39,-1.7 -0.39,-1.7 -0.26,-1.7 -0.241,-1.696 -0.225,-1.685 -0.214,-1.669 -0.21,-1.65 -0.21,-1.65 -0.21,-0.925 -0.206,-0.906 -0.195,-0.89 -0.179,-0.879 -0.16,-0.875 -0.16,-0.875 0.16,-0.875 0.179,-0.879 0.195,-0.89 0.206,-0.906 0.21,-0.925 0.21,-0.925 0.21,-1.65 0.21,-1.65 0.214,-1.669 0.225,-1.685 0.241,-1.696 0.26,-1.7 0.26,-1.7 0.39,-1.7 0.409,-1.696 0.425,-1.685 0.436,-1.669 0.44,-1.65 0.44,-1.65 0.44,-0.925 0.444,-0.906 0.455,-0.89 0.471,-0.879 0.49,-0.875 0.49,-0.875 0.7,-0.875 0.719,-0.871 0.735,-0.86 0.746,-0.844 0.75,-0.825 0.75,-0.825 0.75,0.825 0.746,0.844 0.735,0.86 0.719,0.871 0.7,0.875 0.7,0.875 0.49,0.875 0.471,0.879 0.455,0.89 0.444,0.906 0.44,0.925 0.44,0.925 0.44,1.65 0.436,1.669 0.425,1.685 0.409,1.696 0.39,1.7 0.39,1.7 0.26,1.7 0.241,1.696 0.225,1.685 0.214,1.669 0.21,1.65 0.21,1.65 0.21,1.65 0.21,0.925 0.206,0.906 0.195,0.89 0.179,0.879 0.16,0.875 0.16,0.875 -0.16,0.875 -0.179,0.879 -0.195,0.89 -0.206,0.906 -0.21,0.925 -0.21,0.925 -0.21,1.65 -0.214,1.669 -0.225,1.685 -0.241,1.696 -0.26,1.7 -0.26,1.7 -0.39,1.7 -0.409,1.696 -0.425,1.685 -0.436,1.669 -0.44,1.65 -0.44,1.65 -0.44,0.925 -0.444,0.906 -0.455,0.89 -0.471,0.879 -0.49,0.875 -0.49,0.875 -0.7,0.875 -0.719,0.871 -0.735,0.86 -0.746,0.844 -0.75,0.825 -0.75,0.825 -0.75,-0.825 -0.746,-0.844 -0.735,-0.86 -0.719,-0.871 -0.7,-0.875
  silkscreen extent -1.73,-1.73 1.73,1.73, body extent -1.5,-1.5 1.5,1.5, height 0.77
DRC0010J-MFG [mm]
  rrect42% 0.6x0.24 smd paste+0 mask+0: 1(-1.4,1) 2(-1.4,0.5) 3(-1.4,0) 4(-1.4,-0.5) 5(-1.4,-1) 6(1.4,-1) 7(1.4,-0.5) 8(1.4,0) 9(1.4,0.5) 10(1.4,1)
  round 1.485 smd paste-1000 mask+0: 11(0,0)
  Top Layer region: -0.825,-1.15 -0.818,-1.175 -0.8,-1.193 -0.775,-1.2 -0.775,-1.2 -0.375,-1.2 -0.375,-1.65 -0.368,-1.675 -0.35,-1.693 -0.325,-1.7 -0.325,-1.7 -0.175,-1.7 -0.156,-1.696 -0.14,-1.685 -0.129,-1.669 -0.125,-1.65 -0.125,-1.65 -0.125,-1.2 0.125,-1.2 0.125,-1.65 0.129,-1.669 0.14,-1.685 0.156,-1.696 0.175,-1.7 0.175,-1.7 0.325,-1.7 0.35,-1.693 0.368,-1.675 0.375,-1.65 0.375,-1.65 0.375,-1.2 0.775,-1.2 0.8,-1.193 0.818,-1.175 0.825,-1.15 0.825,-1.15 0.825,1.15 0.818,1.175 0.8,1.193 0.775,1.2 0.775,1.2 0.375,1.2 0.375,1.65 0.368,1.675 0.35,1.693 0.325,1.7 0.325,1.7 0.175,1.7 0.156,1.696 0.14,1.685 0.129,1.669 0.125,1.65 0.125,1.65 0.125,1.2 -0.125,1.2 -0.125,1.65 -0.129,1.669 -0.14,1.685 -0.156,1.696 -0.175,1.7 -0.175,1.7 -0.325,1.7 -0.35,1.693 -0.368,1.675 -0.375,1.65 -0.375,1.65 -0.375,1.2 -0.775,1.2 -0.8,1.193 -0.818,1.175 -0.825,1.15 -0.825,1.15
  silkscreen extent -2.5,-1.55 1.55,1.55, body extent -1.8,-1.8 1.8,1.8, height 0.25
DRL0008A-MFG [mm]
  rrect33% 0.67x0.3 smd paste+0 mask+0: 1(-0.74,0.75) 2(-0.74,0.25) 3(-0.74,-0.25) 4(-0.74,-0.75) 5(0.74,-0.75) 6(0.74,-0.25) 7(0.74,0.25) 8(0.74,0.75)
  silkscreen extent -1.77,-1.28 0.65,1.28, body extent -0.8,-1.05 0.8,1.05, height 0.6
DSG0008A [mm] "SON, 8-Leads, Body 2x2mm, Pitch 0.5mm, Thermal Pad 1.6x0.9mm, TI Recommended"
  rrect40% 0.5x0.25 smd: 1(-0.95,0.75) 2(-0.95,0.25) 3(-0.95,-0.25) 4(-0.95,-0.75) 5(0.95,-0.75) 6(0.95,-0.25) 7(0.95,0.25) 8(0.95,0.75)
  rrect14% 0.9x0.7 on Bottom Paste: 9(0,-0.45) 9(0,0.45)
  rrect11% 0.9x1.6 smd paste-0.45: 9(0,0)
  silkscreen extent -1.07,-1.15 1.07,1.15, body extent -1,-1 1,1, height 0.77
Epson_FC-135 [mm] "SMD, 2-Leads, Body 3.2x1.5mm"
  rect 1x1.8 smd: 1(-1.25,0) 2(1.25,0)
  silkscreen extent -0.35,-0.8 0.35,0.8, body extent -1.65,-0.8 1.65,0.8, height 0.9
FCC_disclaimer [mil]
Fiducial10-20 [mm]
  round 1 smd mask+0.5: 1(0,0)
  Top Layer keep-out circle w1.178: c0,0 r0.5
FP-107AXZ050M_RADIAL-MFG [mm]
  rrect5% 4x2 smd paste+0 mask+0: 1(-3.6,0) 2(3.6,0)
  silkscreen extent -6.28,-4.25 4.25,4.25, body extent -5.85,-4.5 5.85,4.5, height 0.25
FP-C3225X7R2A225K230AB_1210-MFG [mm]
  rrect9% 1.1x2.2 smd paste+0 mask+0: 1(-1.65,0) 2(1.65,0)
  silkscreen extent -0.72,-1.4 0.72,1.4, body extent -1.6,-1.25 1.6,1.25, height 2.5
FP-GRM21BR61H106ME43L_0805-MFG [mm]
  rrect14% 0.7x1.3 smd paste+0 mask+0: 1(-0.95,0) 2(0.95,0)
  silkscreen extent -0.23,-0.72 0.23,0.72, body extent -1,-0.63 1,0.63, height 1.45
FP-TNPW060312K0BYEN_0603-MFG [mm]
  rrect20% 0.5x0.9 smd paste+0 mask+0: 1(-0.75,0) 2(0.75,0)
  silkscreen extent -0.13,-0.48 0.13,0.48, body extent -1.1,-0.58 1.1,0.58, height 0.25
FP-X1E0000210179_TSX-3225-MFG [mm]
  rrect9% 1.4x1.15 smd paste+0 mask+0: 1(-1.1,-0.8) 2(1.1,-0.8) 3(1.1,0.8) 4(-1.1,0.8)
  silkscreen extent -1.22,-2.05 0,1.33, body extent -1.6,-1.25 1.6,1.25, height 0.6
Harwin_M20-87702 [mm] "Header, 2.54mm, 2x1,  SMT"
  rect 1x2.51 smd: 1(-1.27,1.655) 2(1.27,-1.655)
  silkscreen extent -2.9,-1.27 2.54,1.27, body extent -2.54,-2.54 2.54,2.54, height 9.93
Keystone5000 [mil] "For Keystone 500x miniature loop terminals"
  round 80 hole 40: 1(0,0)
  silkscreen extent -52,-52 52,52, body extent -49,-49 49,49, height 182
Keystone5001 [mil] "For Keystone 500x miniature loop terminals"
  round 80 hole 40: 1(0,0)
  silkscreen extent -52,-52 52,52, body extent -49,-49 49,49, height 182
Keystone5117 [mil] "For Keystone 500x miniature loop terminals"
  round 80 hole 40: 1(0,0)
  silkscreen extent -52,-52 52,52, body extent -49,-49 49,49, height 182
Keystone5122 [mil] "Keystone Compact loops"
  round 87 hole 63: 1(0,0)
  silkscreen extent -70,-70 70,70, body extent -63,-63 62,63, height 225
Keystone_1902C [mil] "Hex Standoff, 4-40 threaded, nylon"
  round 1 on Mech4: 0(0,0)
  body extent -145,-126 146,126, height 501
LP0003A [mm] "TO, Flat Index; 3 In-Line, Formed Axial Leads; Body Dia. 4.8mm; Leads 0.56 x 0.41 mm (max)"
  rrect7% 1.4x1.4 hole 0.9: 1(0,2.54)
  round 1.4 hole 0.9: 2(0,0) 3(0,-2.54)
  silkscreen extent -1.35,-2.41 2.65,2.95, body extent -1.33,-2.83 2.35,2.83, height 9.01
LTST-C191_Green [mm] "Lite-On"
  rect 0.8x0.8 smd: 1(-0.75,0) 2(0.75,0)
  silkscreen extent -1.1,-0.8 1.8,0.8, body extent -0.85,-0.45 0.85,0.45, height 0.65
LTST-C191_Orange [mm] "SMD, 2-Leads, Body 1.6x0.8mm"
  rect 0.8x0.8 smd: 1(-0.75,0) 2(0.75,0)
  silkscreen extent -1.1,-0.8 1.8,0.8, body extent -0.85,-0.45 0.85,0.45, height 0.65
LTST-C191_Red [mm] "SMD, 2-Leads, Body1.6x0.8mm"
  rect 0.8x0.8 smd: 1(-0.75,0) 2(0.75,0)
  silkscreen extent -1.2,-0.8 1.85,0.8, body extent -0.85,-0.45 0.85,0.45, height 0.66
MSS1210 [mm] "Coilcraft MSS1210 series"
  rect 3x5.5 smd: 1(-4.75,0) 2(4.75,0)
  silkscreen extent -6.3,-6.3 6.3,6.3, body extent -6.15,-6.15 6.15,6.15, height 10.2
NPI32C [mm] "NIC COMPONENTS"
  rect 1.3x3.3 smd: 1(-1.2,0) 2(1.2,0)
  body extent -1.9,-1.65 1.9,1.65, height 2.4
"NY PMS 440 0025 PH" [mm] "4-40 nylon screw and mounting hole"
  round 8 hole 3.2: 1(0,0)
  body extent -3.3,-3.3 3.3,3.3, height 2.69
Phoenix_1714955 [mm] "Terminal Block, 2x1, 6.35mm, TH"
  rect 1.8x1.8 hole 1.3: 1(-3.175,0)
  round 1.8 hole 1.3: 2(3.175,0)
  silkscreen extent -6.7,-7.9 6.35,4.6, body extent -6.92,-7.9 6.35,4.6, height 21.5
Phoenix_1714968 [mm] "Phoenix"
  rect 2x2 hole 1.3: 1(-6.35,0)
  round 2 hole 1.3: 2(0,0) 3(6.35,0)
  silkscreen extent -10.34,-7.88 9.57,4.6, body extent -10.06,-7.9 9.56,4.6, height 21.5
Phoenix_1729018 [mm] "Phoenix Contact"
  rect 1.905x1.905 hole 1.3: 1(-2.5,0)
  round 1.9 hole 1.3: 2(2.5,0)
  silkscreen extent -5.56,-4.08 5.01,4.07, body extent -5.56,-4.08 5.01,4.07, height 10
Phoenix_1792892 [mm] "Terminal Block, 5mm, 5x1, R/A, TH"
  rrect50% 1.7x1.7 hole 1.2: 1(-10,0)
  round 1.7 hole 1.2: 2(-5,0) 3(0,0) 4(5,0) 5(10,0)
  silkscreen extent -12.8,-4.95 12.5,5.55, body extent -12.5,-4.95 12.5,5.55, height 13.6
PM0064A-MFG [mm]
  rrect33% 1.5x0.3 smd paste+0 mask+0: 1(-5.7,3.75) 2(-5.7,3.25) 3(-5.7,2.75) 4(-5.7,2.25) 5(-5.7,1.75) 6(-5.7,1.25) 7(-5.7,0.75) 8(-5.7,0.25) 9(-5.7,-0.25) 10(-5.7,-0.75) 11(-5.7,-1.25) 12(-5.7,-1.75) 13(-5.7,-2.25) 14(-5.7,-2.75) 15(-5.7,-3.25) 16(-5.7,-3.75) 33(5.7,-3.75) 34(5.7,-3.25) 35(5.7,-2.75) 36(5.7,-2.25) 37(5.7,-1.75) 38(5.7,-1.25) 39(5.7,-0.75) 40(5.7,-0.25) 41(5.7,0.25) 42(5.7,0.75) 43(5.7,1.25) 44(5.7,1.75) 45(5.7,2.25) 46(5.7,2.75) 47(5.7,3.25) 48(5.7,3.75)
  rrect33% 0.3x1.5 smd paste+0 mask+0: 17(-3.75,-5.7) 18(-3.25,-5.7) 19(-2.75,-5.7) 20(-2.25,-5.7) 21(-1.75,-5.7) 22(-1.25,-5.7) 23(-0.75,-5.7) 24(-0.25,-5.7) 25(0.25,-5.7) 26(0.75,-5.7) 27(1.25,-5.7) 28(1.75,-5.7) 29(2.25,-5.7) 30(2.75,-5.7) 31(3.25,-5.7) 32(3.75,-5.7) 49(3.75,5.7) 50(3.25,5.7) 51(2.75,5.7) 52(2.25,5.7) 53(1.75,5.7) 54(1.25,5.7) 55(0.75,5.7) 56(0.25,5.7) 57(-0.25,5.7) 58(-0.75,5.7) 59(-1.25,5.7) 60(-1.75,5.7) 61(-2.25,5.7) 62(-2.75,5.7) 63(-3.25,5.7) 64(-3.75,5.7)
  silkscreen extent -7.13,-5.1 5.1,5.1, body extent -6,-6 6,6, height 1.6
RGF0040E-MFG [mm]
  rrect40% 0.6x0.25 smd paste+0 mask+0: 1(-2.4,2.75) 2(-2.4,2.25) 3(-2.4,1.75) 4(-2.4,1.25) 5(-2.4,0.75) 6(-2.4,0.25) 7(-2.4,-0.25) 8(-2.4,-0.75) 9(-2.4,-1.25) 10(-2.4,-1.75) 11(-2.4,-2.25) 12(-2.4,-2.75) 21(2.4,-2.75) 22(2.4,-2.25) 23(2.4,-1.75) 24(2.4,-1.25) 25(2.4,-0.75) 26(2.4,-0.25) 27(2.4,0.25) 28(2.4,0.75) 29(2.4,1.25) 30(2.4,1.75) 31(2.4,2.25) 32(2.4,2.75)
  rrect40% 0.25x0.6 smd paste+0 mask+0: 13(-1.75,-3.4) 14(-1.25,-3.4) 15(-0.75,-3.4) 16(-0.25,-3.4) 17(0.25,-3.4) 18(0.75,-3.4) 19(1.25,-3.4) 20(1.75,-3.4) 33(1.75,3.4) 34(1.25,3.4) 35(0.75,3.4) 36(0.25,3.4) 37(-0.25,3.4) 38(-0.75,3.4) 39(-1.25,3.4) 40(-1.75,3.4)
  rrect3% 3.7x5.7 smd paste-1000 mask+0: 41(0,0)
  silkscreen extent -3.4,-3.55 2.55,3.55, body extent -2.5,-3.5 2.5,3.5, height 1
RTE0016J [mm] "WQFN-16"
  rrect42% 0.6x0.24 smd: 1(-1.4,0.75) 2(-1.4,0.25) 3(-1.4,-0.25) 4(-1.4,-0.75) 9(1.4,-0.75) 10(1.4,-0.25) 11(1.4,0.25) 12(1.4,0.75)
  rrect42% 0.24x0.6 smd: 5(-0.75,-1.4) 6(-0.25,-1.4) 7(0.25,-1.4) 8(0.75,-1.4) 13(0.75,1.4) 14(0.25,1.4) 15(-0.25,1.4) 16(-0.75,1.4)
  rrect6% 1.66x1.66 smd paste-0.075: 17(0,0)
  silkscreen extent -1.5,-1.5 1.5,1.5, body extent -1.5,-1.5 1.5,1.5, height 0.8
Samtec_FTSH-105-01-x-DV-K [mm] "Header(Shrouded), 1.27mm, 5x2, SMT"
  rect 2.79x0.74 smd: 1(-2.035,2.54) 2(2.035,2.54) 3(-2.035,1.27) 4(2.035,1.27) 5(-2.035,0) 6(2.035,0) 7(-2.035,-1.27) 8(2.035,-1.27) 9(-2.035,-2.54) 10(2.035,-2.54)
  silkscreen extent -3.73,-3.48 3.73,3.48, body extent -2.92,-3.18 2.92,3.17, height 6.13
SM_RADIAL_G [mm] "10 x 10.2mm:  Panasonic G"
  rect 4.1x2 smd: 1(-4.35,0) 2(4.35,0)
  silkscreen extent -5.35,-5.35 5.35,5.35, body extent -5.25,-5.25 5.25,5.25, height 10.5
SMA [mm] "Molded Diode, 2-Leads, Body 4.3x2.6mm, IPC Medium Density, based on OnSemi component dimensions and land pattern"
  rect 2x2 smd: 1(-2,0) 2(2,0)
  silkscreen extent -3.66,-1.57 2.79,1.57, body extent -2.6,-1.3 2.6,1.3, height 2.42
SOT-23 [mm] "SOT23, 3-Leads, Body 2.9x1.3mm, Pitch 0.95mm, Lead Span 2.5mm, IPC Medium Density"
  rrect50% 1x0.6 smd: 1(-1.2,0.95) 2(-1.2,-0.95) 3(1.2,0)
  silkscreen extent -1.62,-1.5 0.7,1.5, body extent -1.16,-1.45 1.21,1.45, height 1
SW_1103M2S3CQE2 [mm] "TH, 3-Leads, Body 12.7x6.6mm, Pitch 4.7mm"
  rect 2.35x2.35 hole 1.85: 1(-4.7,0)
  round 2.35 hole 1.85: 2(0,0) 3(4.7,0)
  silkscreen extent -6.35,-4 6.35,3.3, body extent -6.35,-3.3 6.35,3.3, height 11.8
TERM_BLK_ED555-3DS [mm]
  rect 2.54x2.54 hole 1.27: 1(0,0)
  round 2.54 hole 1.27: 2(3.5,0) 3(7,0)
  silkscreen extent -2.36,-4.09 8.75,2.67, body extent -1.75,-3.83 8.75,2.67, height 8.2
TI_Stacked_Overlay_Small [mil]
  silkscreen extent -418,-98 418,98
TNPW0603 [mm] "Vishay"
  rect 0.5x0.9 smd: 1(-0.75,0) 2(0.75,0)
  silkscreen extent -0.2,-0.6 0.2,0.6, body extent -0.85,-0.47 0.85,0.47, height 0.55
WE-HCI_1050 [mm] "SMT Flat Wire High Current Inductor, body 10.2x10.2mm"
  rect 4x3.85 smd: 1(0,3.825) 2(0,-3.825)
  silkscreen extent -5.35,-5.35 5.35,5.35, body extent -5.1,-5.5 5.1,5.5, height 5
WEEE_Minimum [mil] "WEEElie bin"
  silkscreen extent -95,-172 99,104

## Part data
C1 C2 C3 C6: library part CMP-0006439-2, "CAP, CERM, 22 pF, 50 V, +/- 5%, C0G/NP0, 0402", Cap_Case=0402, Manufacturer=MuRata, Supplier Part Number 1=81-GRM1555C1H220JA1D, TempCo=C0G/NP0, Tolerance_%=5%, Value1=Unknown, Value2=50V, ValueDisplayed=22pF
C4: library part CMP-0007304-5, "CAP, CERM, 10 uF, 6.3 V, +/- 20%, X5R, 0603", Cap_Case=0603, Manufacturer=MuRata, Supplier Part Number 1=490-7316-1-ND, TempCo=X5R, Tolerance_%=20%, Value1=Unknown, Value2=6.3V, ValueDisplayed=10uF
C5 C18: library part CMP-0006531-2, "CAP, CERM, 0.1 uF, 6.3 V, +/- 10%, X5R, 0402", Cap_Case=0402, Manufacturer=MuRata, Supplier Part Number 1=GRM155R60J104KA01D-ND, TempCo=X5R, Tolerance_%=10%, Value1=Unknown, Value2=6.3V, ValueDisplayed=0.1uF
C7: library part CMP-0006551-2, "CAP, CERM, 0.47 uF, 6.3 V, +/- 10%, X5R, 0402", Cap_Case=0402, Manufacturer=MuRata, Supplier Part Number 1=490-3266-1-ND, TempCo=X5R, Tolerance_%=10%, Value1=Unknown, Value2=6.3V, ValueDisplayed=0.47uF
C8: library part CMP-0006530-2, "CAP, CERM, 0.01 uF, 6.3 V, +/- 10%, X5R, 0402", Cap_Case=0402, Manufacturer=MuRata, Supplier Part Number 1=GRM155R60J103KA01D-ND, TempCo=X5R, Tolerance_%=10%, Value1=Unknown, Value2=6.3V, ValueDisplayed=0.01uF
C9: library part CMP-0007006-5, "CAP, CERM, 1 uF, 25 V, +/- 10%, X5R, 0603", Cap_Case=0603, Manufacturer=TDK, Supplier Part Number 1=445-5146-1-ND, TempCo=X5R, Tolerance_%=10%, Value1=Unknown, Value2=25V, ValueDisplayed=1uF
C10: library part CMP-0093755-1, "Aluminum Electrolytic Capacitors Radial, Can - SMD 2.321Ohm @ 120Hz 2000 Hrs @ 105°C", Digikey Part Number=1572-1038-1-ND, Leakage Current=50uA, Manufacturer="Cornell Dubilier", Mouser Part Number=598-107AXZ050M, Operating Temperature Range="-55°C to +105°C", Tolerance_%=20%, ValueDisplayed=100uF
C11 C14: library part CMP-0007010-5, "CAP, CERM, 0.1 uF, 50 V, +/- 10%, X5R, 0603", Cap_Case=0603, Manufacturer=TDK, Supplier Part Number 1=445-7456-1-ND, TempCo=X5R, Tolerance_%=10%, Value1="0.0296 ohm", Value2=50V, ValueDisplayed=0.1uF
C12 C53: library part CMP-0095280-1, "Chip Multilayer Ceramic Capacitors for General Purpose, 0805, 10uF, X5R, 15%, 20%, 50V", Manufacturer=Murata, Operating Temperature Range="-55°C to +85°C", TempCo=15%, Temperature Characteristic=X5R, Tolerance_%=20%, ValueDisplayed=10uF
C13: library part CMP-0007364-4, "CAP, CERM, 0.47 uF, 6.3 V, +/- 10%, X7R, 0603", Cap_Case=0603, Manufacturer=MuRata, Supplier Part Number 1=GRM188R70J474KA01D-ND, TempCo=X7R, Tolerance_%=10%, Value1=Unknown, Value2=6.3V, ValueDisplayed=0.47uF
C15: library part CMP-0006532-2, "CAP, CERM, 1 uF, 6.3 V, +/- 10%, X5R, 0402", Cap_Case=0402, Manufacturer=MuRata, Supplier Part Number 1=490-1320-1-ND, TempCo=X5R, Tolerance_%=10%, Value1=Unknown, Value2=6.3V, ValueDisplayed=1uF
C16: library part CMP-0006617-2, "CAP, CERM, 0.047 uF, 50 V, +/- 20%, X5R, 0402", Cap_Case=0402, Manufacturer=MuRata, Supplier Part Number 1=81-GRM155R61H473ME4D, TempCo=X5R, Tolerance_%=20%, Value1=Unknown, Value2=50V, ValueDisplayed=0.047uF
C17: library part CMP-0006868-5, "CAP, CERM, 1 uF, 16 V, +/- 10%, X5R, 0603", Cap_Case=0603, Manufacturer=Kemet, Supplier Part Number 1=399-5090-1-ND, TempCo=X5R, Tolerance_%=10%, Value1=Unknown, Value2=16V, ValueDisplayed=1uF
C19: library part CMP-0860267-1, "CAP, CERM, 22 µF, 35 V,+/- 20%, X5R, 0805", Cap_Case=0805, Manufacturer=Arrow, TempCo=X5R, Tolerance_%=20%, Value2=35V, ValueDisplayed=22µF
C20 C21 C22: library part CMP-0007205-4, "CAP, CERM, 30 pF, 50 V, +/- 5%, C0G/NP0, 0603", Cap_Case=0603, Manufacturer=MuRata, Supplier Part Number 1=490-1414-1-ND, TempCo=C0G/NP0, Tolerance_%=5%, Value1=Unknown, Value2=50V, ValueDisplayed=30pF
C23 C24 C25: library part CMP-0006826-4, "CAP, CERM, 1000 pF, 16 V, +/- 10%, X7R, 0603", Cap_Case=0603, Manufacturer="Wurth Elektronik", Supplier Part Number 1=710-885012206034, TempCo=X7R, Tolerance_%=10%, Value1=Unknown, Value2=16V, ValueDisplayed=1000pF
C26: library part CMP-0006608-2, "CAP, CERM, 1 uF, 25 V, +/- 10%, X5R, 0402", Cap_Case=0402, Manufacturer=MuRata, Supplier Part Number 1=490-10017-1-ND, TempCo=X5R, Tolerance_%=10%, Value1=Unknown, Value2=25V, ValueDisplayed=1uF
C27: library part CMP-0006675-2, "CAP, CERM, 0.1 uF, 50 V, +/- 20%, X7R, 0402", Cap_Case=0402, Manufacturer=MuRata, Supplier Part Number 1=490-10701-1-ND, TempCo=X7R, Tolerance_%=20%, Value1=Unknown, Value2=50V, ValueDisplayed=0.1uF
C28: library part CMP-0085846-1, "CAP, CERM, 0.1 µF, 6.3 V,+/- 10%, X5R, 0603", Cap_Case=0603, Manufacturer=Kemet, TempCo=X5R, Tolerance_%=10%, Value2=6.3V, ValueDisplayed=0.1µF
C29 C30 C54: library part CMP-0006562-2, "CAP, CERM, 0.1 uF, 10 V, +/- 10%, X5R, 0402", Cap_Case=0402, Manufacturer=MuRata, Supplier Part Number 1=490-1318-1-ND, TempCo=X5R, Tolerance_%=10%, Value1=Unknown, Value2=10V, ValueDisplayed=0.1uF
C31: library part CMP-0095533-2, "CAP, CERM, 2.2 uF, 100 V, +/- 10%, X7R, 1210", Manufacturer=TDK, Operating Temperature Range="-55°C  to +125°C", TempCo=0.15, Temperature Characteristic=X7R, Tolerance_%=0.1%, ValueDisplayed=2.2uF
C32: library part CMP-0007886-2, "CAP, CERM, 0.1 uF, 100 V, +/- 10%, X7R, 0805", Cap_Case=0805, Manufacturer=TDK, Supplier Part Number 1=445-1418-1-ND, TempCo=X7R, Tolerance_%=10%, Value1="0.020726 ohm", Value2=100V, ValueDisplayed=0.1uF
C33 C34: library part CMP-0007061-4, "CAP, CERM, 0.068 uF, 100 V, +/- 10%, X7S, 0603", Cap_Case=0603, Manufacturer=TDK, Supplier Part Number 1=445-6034-1-ND, TempCo=X7S, Tolerance_%=10%, Value1="0.074084 ohm", Value2=100V, ValueDisplayed=0.068uF
C35: library part CMP-0006333-2, "CAP, CERM, 0.01 uF, 100 V, +/- 10%, X7S, AEC-Q200 Grade 1, 0402", Cap_Case=0402, Manufacturer=TDK, Supplier Part Number 1=445-6910-1-ND, TempCo=X7S, Tolerance_%=10%, Value1="0.410191 ohm", Value2=100V, ValueDisplayed=0.01uF
C36: library part CMP-0006641-2, "CAP, CERM, 0.1 uF, 16 V, +/- 10%, X7R, 0402", Cap_Case=0402, Manufacturer=MuRata, Supplier Part Number 1=490-3261-1-ND, TempCo=X7R, Tolerance_%=10%, Value1=Unknown, Value2=16V, ValueDisplayed=0.1uF
C37 C38: library part CMP-0011188-2, "CAP, AL, 100 uF, 63 V, +/- 20%, 0.35 ohm, AEC-Q200 Grade 2, SMD", Cap_Case=G, Manufacturer=Panasonic, Supplier Part Number 1=PCE3819CT-ND, Tolerance_%=20%, Value1="0.35 ohm", Value2=63V, ValueDisplayed=100uF
C39: library part CMP-0007840-2, "CAP, CERM, 4.7 uF, 50 V, +/- 10%, X5R, 0805", Cap_Case=0805, Manufacturer=TDK, Supplier Part Number 1=445-5980-1-ND, TempCo=X5R, Tolerance_%=10%, Value1="0.002346 ohm", Value2=50V, ValueDisplayed=4.7uF
C40 C41: library part CMP-0012141-3, "CAP, Aluminum Polymer, 10 uF, 50 V, +/- 20%, 0.04 ohm, F61 SMD", Manufacturer=Panasonic, Tolerance_%=20%, Value1="0.04 ohm", Value2=50V, ValueDisplayed=10uF
C42: library part CMP-0007011-5, "CAP, CERM, 1 uF, 50 V, +/- 10%, X5R, 0603", Cap_Case=0603, Manufacturer=TDK, Supplier Part Number 1=445-7468-1-ND, TempCo=X5R, Tolerance_%=10%, Value1="0.005522 ohm", Value2=50V, ValueDisplayed=1uF
C43: library part CMP-0008658-2, "CAP, CERM, 10 uF, 50 V, +/- 10%, X5R, 1206", Cap_Case=1206_180, Manufacturer=TDK, Supplier Part Number 1=445-5998-1-ND, TempCo=X5R, Tolerance_%=10%, Value1="0.002229 ohm", Value2=50V, ValueDisplayed=10uF
C44: library part CMP-0007078-4, "CAP, CERM, 0.1 uF, 50 V, +/- 10%, X7R, AEC-Q200 Grade 1, 0603", Cap_Case=0603, Manufacturer=TDK, Supplier Part Number 1=445-5666-1-ND, TempCo=X7R, Tolerance_%=10%, Value1="0.0296 ohm", Value2=50V, ValueDisplayed=0.1uF
C45: library part CMP-0006632-2, "CAP, CERM, 0.033 uF, 10 V, +/- 10%, X7R, 0402", Cap_Case=0402, Manufacturer=MuRata, Supplier Part Number 1=490-1315-1-ND, TempCo=X7R, Tolerance_%=10%, Value1=Unknown, Value2=10V, ValueDisplayed=0.033uF
C46: library part CMP-0006629-2, "CAP, CERM, 0.1 uF, 10 V, +/- 10%, X7R, 0402", Cap_Case=0402, Manufacturer=MuRata, Supplier Part Number 1=GRM155R71A104KA01D-ND, TempCo=X7R, Tolerance_%=10%, Value1=Unknown, Value2=10V, ValueDisplayed=0.1uF
C47: library part CMP-0007012-5, "CAP, CERM, 0.15 uF, 50 V, +/- 10%, X5R, 0603", Cap_Case=0603, Manufacturer=TDK, Supplier Part Number 1=445-7458-1-ND, TempCo=X5R, Tolerance_%=10%, Value1="0.028863 ohm", Value2=50V, ValueDisplayed=0.15uF
C48: library part CMP-0007436-4, "CAP, CERM, 0.012 uF, 50 V, +/- 10%, X7R, 0603", Cap_Case=0603, Manufacturer=MuRata, Supplier Part Number 1=490-1513-1-ND, TempCo=X7R, Tolerance_%=10%, Value1=Unknown, Value2=50V, ValueDisplayed=0.012uF
C49: library part CMP-0009662-3, "CAP, CERM, 47 pF, 25 V, +/- 5%, C0G/NP0, 0201", Cap_Case=0201, Manufacturer=MuRata, Supplier Part Number 1=490-1256-1-ND, TempCo=C0G/NP0, Tolerance_%=5%, Value1=Unknown, Value2=25V, ValueDisplayed=47pF
C50: library part CMP-0011330-2, "CAP, AL, 100 uF, 63 V, +/- 20%, 0.25 ohm, SMD", Cap_Case=KE0, Manufacturer=Chemi-Con, Supplier Part Number 1=565-2336-1-ND, Tolerance_%=20%, Value1="0.25 ohm", Value2=63V, ValueDisplayed=100uF
C51: library part CMP-0009211-2, "CAP, CERM, 47 uF, 16 V, +/- 10%, X5R, 1210", Cap_Case=1210, Manufacturer=MuRata, Supplier Part Number 1=GRM32ER61C476KE15L-ND, TempCo=X5R, Tolerance_%=10%, Value1=Unknown, Value2=16V, ValueDisplayed=47uF
C52 C55: library part CMP-0006674-2, "CAP, CERM, 0.01 uF, 50 V, +/- 10%, X7R, 0402", Cap_Case=0402, Manufacturer=MuRata, Supplier Part Number 1=490-4516-1-ND, TempCo=X7R, Tolerance_%=10%, Value1=Unknown, Value2=50V, ValueDisplayed=0.01uF
D1: library part CMP-0002891-3, "LED, Green, SMD", Color=green, Manufacturer=Lite-On, Value1=W, Value2=3.2V
D2: library part CMP-0029239-3, "Diode, Switching-Bridge, 100 V, 1.5 A, DF-S", Manufacturer=Vishay-Semiconductor, Value1=1.5A, Value2=1.1V
D3: library part CMP-0084964-1, "Diode, TVS, Uni, 40 V, 64.5 Vc, 400 W, 6.2 A, SMA", Manufacturer=Littelfuse, Value1=64.5V
D4 D5: library part CMP-0002950-3, "LED, Red, SMD", Color=Red, Manufacturer=Lite-On, Power_TotalModule=75mW, Value1=0.075W, Value2=2V
D6: library part CMP-0002952-2, "LED, Orange, SMD", Color=Orange, Manufacturer=Lite-On, Power_TotalModule=75mW, Supplier Part Number 1=160-1445-1-ND, Value1=0.075W, Value2=2V
FID1 FID2 FID3: library part CMP-0077181-1, "Fiducial mark.  There is nothing to buy or mount.", Manufacturer=N/A
H2 H5 H8 H11: library part CMP-0003610-1, "Standoff, Hex, 0.5\"L #4-40 Nylon", Manufacturer=Keystone, Supplier Part Number 1=36-1902C-ND
H3 H6 H9 H12: library part CMP-0003617-1, "Machine Screw, Round, #4-40 x 1/4, Nylon, Philips panhead", Manufacturer="B&F Fastener Supply", Supplier Part Number 1=H542-ND
J1 J3 J4 J9 J11 J13 J14 J17 J20 J23: library part CMP-0075288-1, "Header, 2.54mm, 2x1, Tin,  SMT", Color=Black, Current_A=3A, Manufacturer=Harwin, Supplier Part Number 1=952-1913-ND, Voltage_V=250V
J2: library part CMP-0075670-2, "Header (Shrouded), 1.27mm, 5x2, Gold, SMT", Color=Black, Current_A=3.3A, Manufacturer=Samtec, Supplier Part Number 1=SAM8796-ND
J5 J6: library part CMP-0055505-1, "Terminal Block, 2x1, 6.35mm, Green, TH", Color=Green, Manufacturer="Phoenix Contact", Supplier Part Number 1=277-1269-ND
